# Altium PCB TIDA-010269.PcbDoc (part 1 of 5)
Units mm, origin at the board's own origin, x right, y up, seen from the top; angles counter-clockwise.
Board outline 87.61 x 53.51 mm, 8 copper layers (Top Layer, GND1, Signal 1, Power 1, Power 2, Signal 2, Layer 1, Bottom Layer), stack 1.645 mm thick; 482 components, 227 nets, 1562 pads, 953 vias.
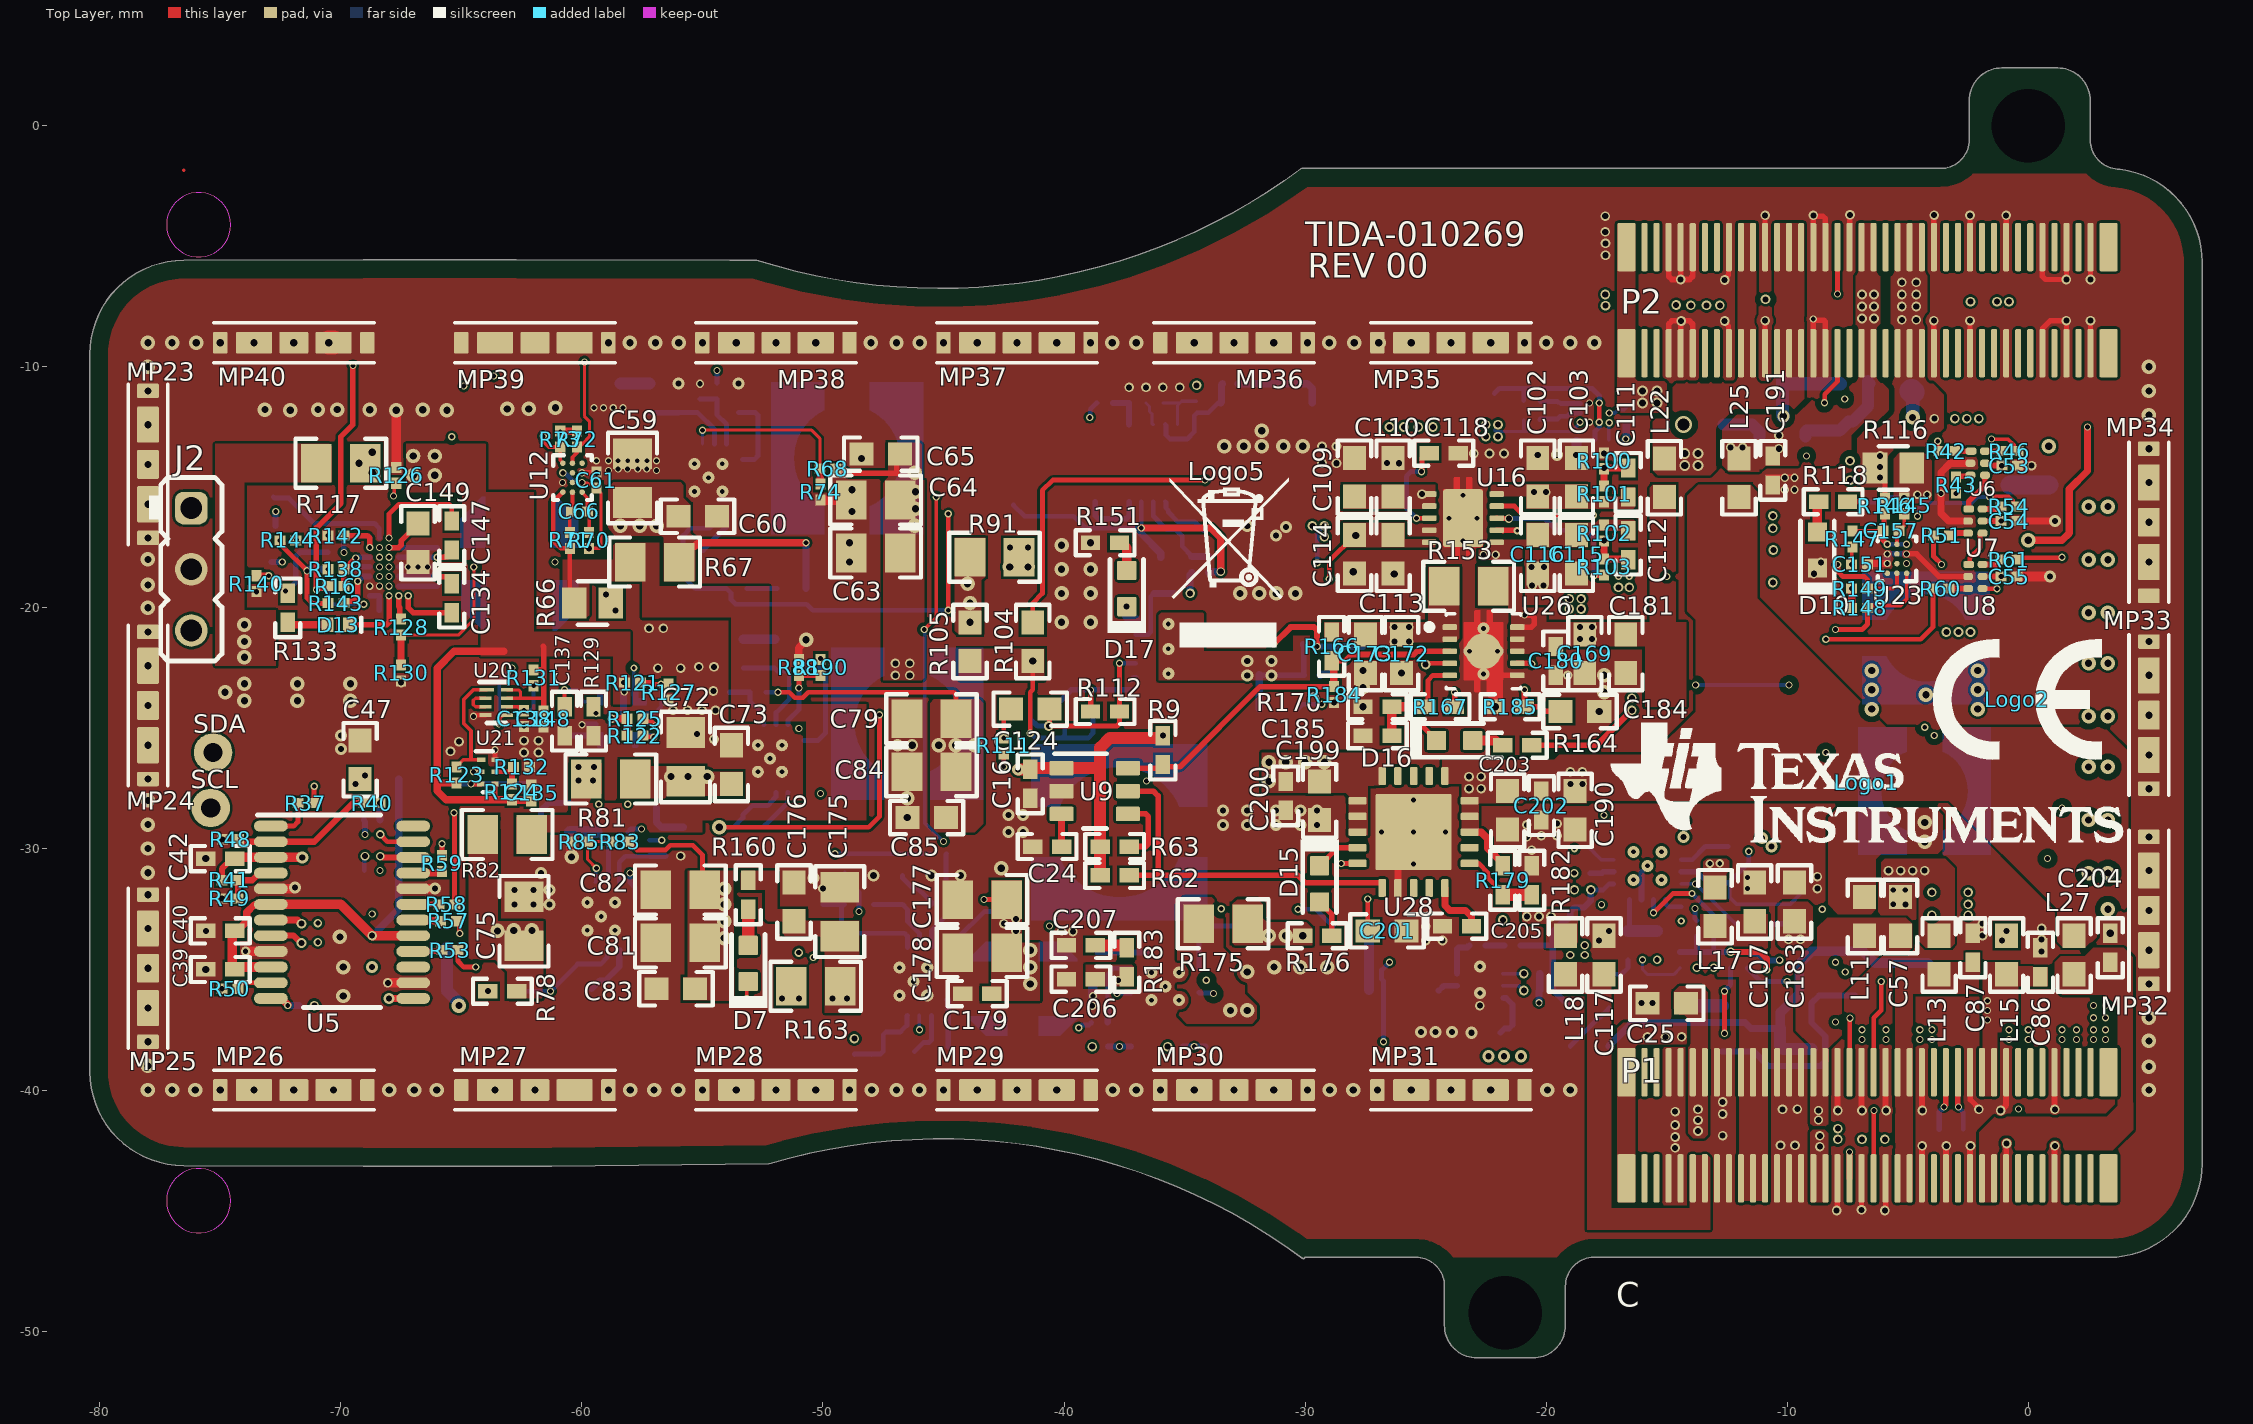
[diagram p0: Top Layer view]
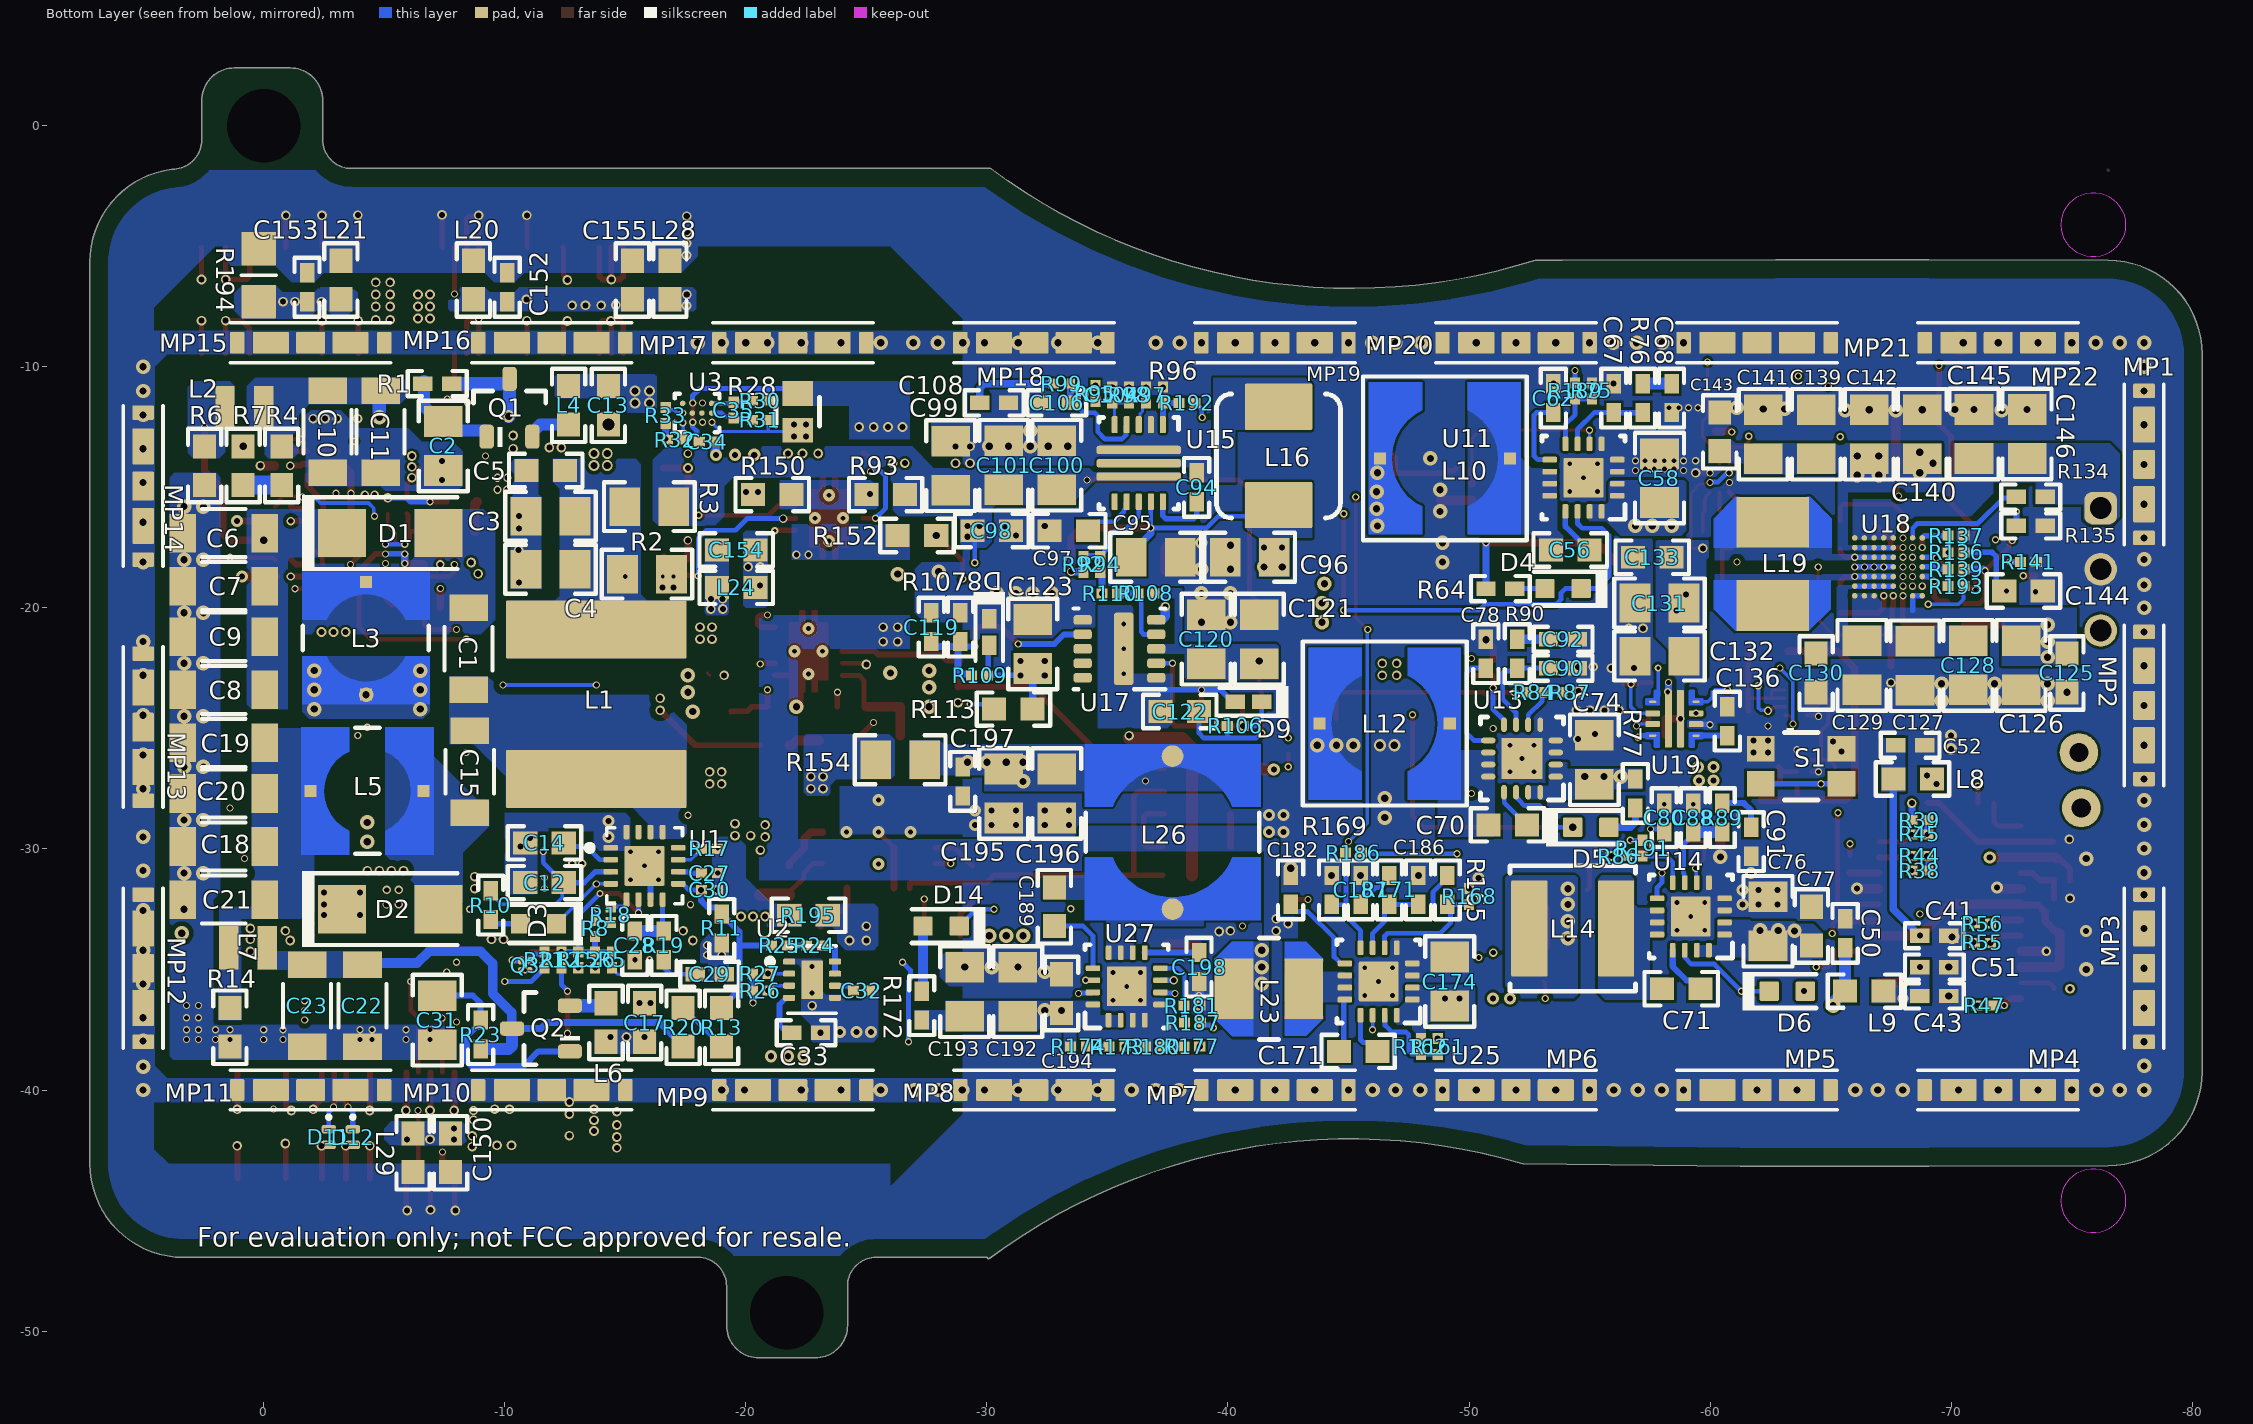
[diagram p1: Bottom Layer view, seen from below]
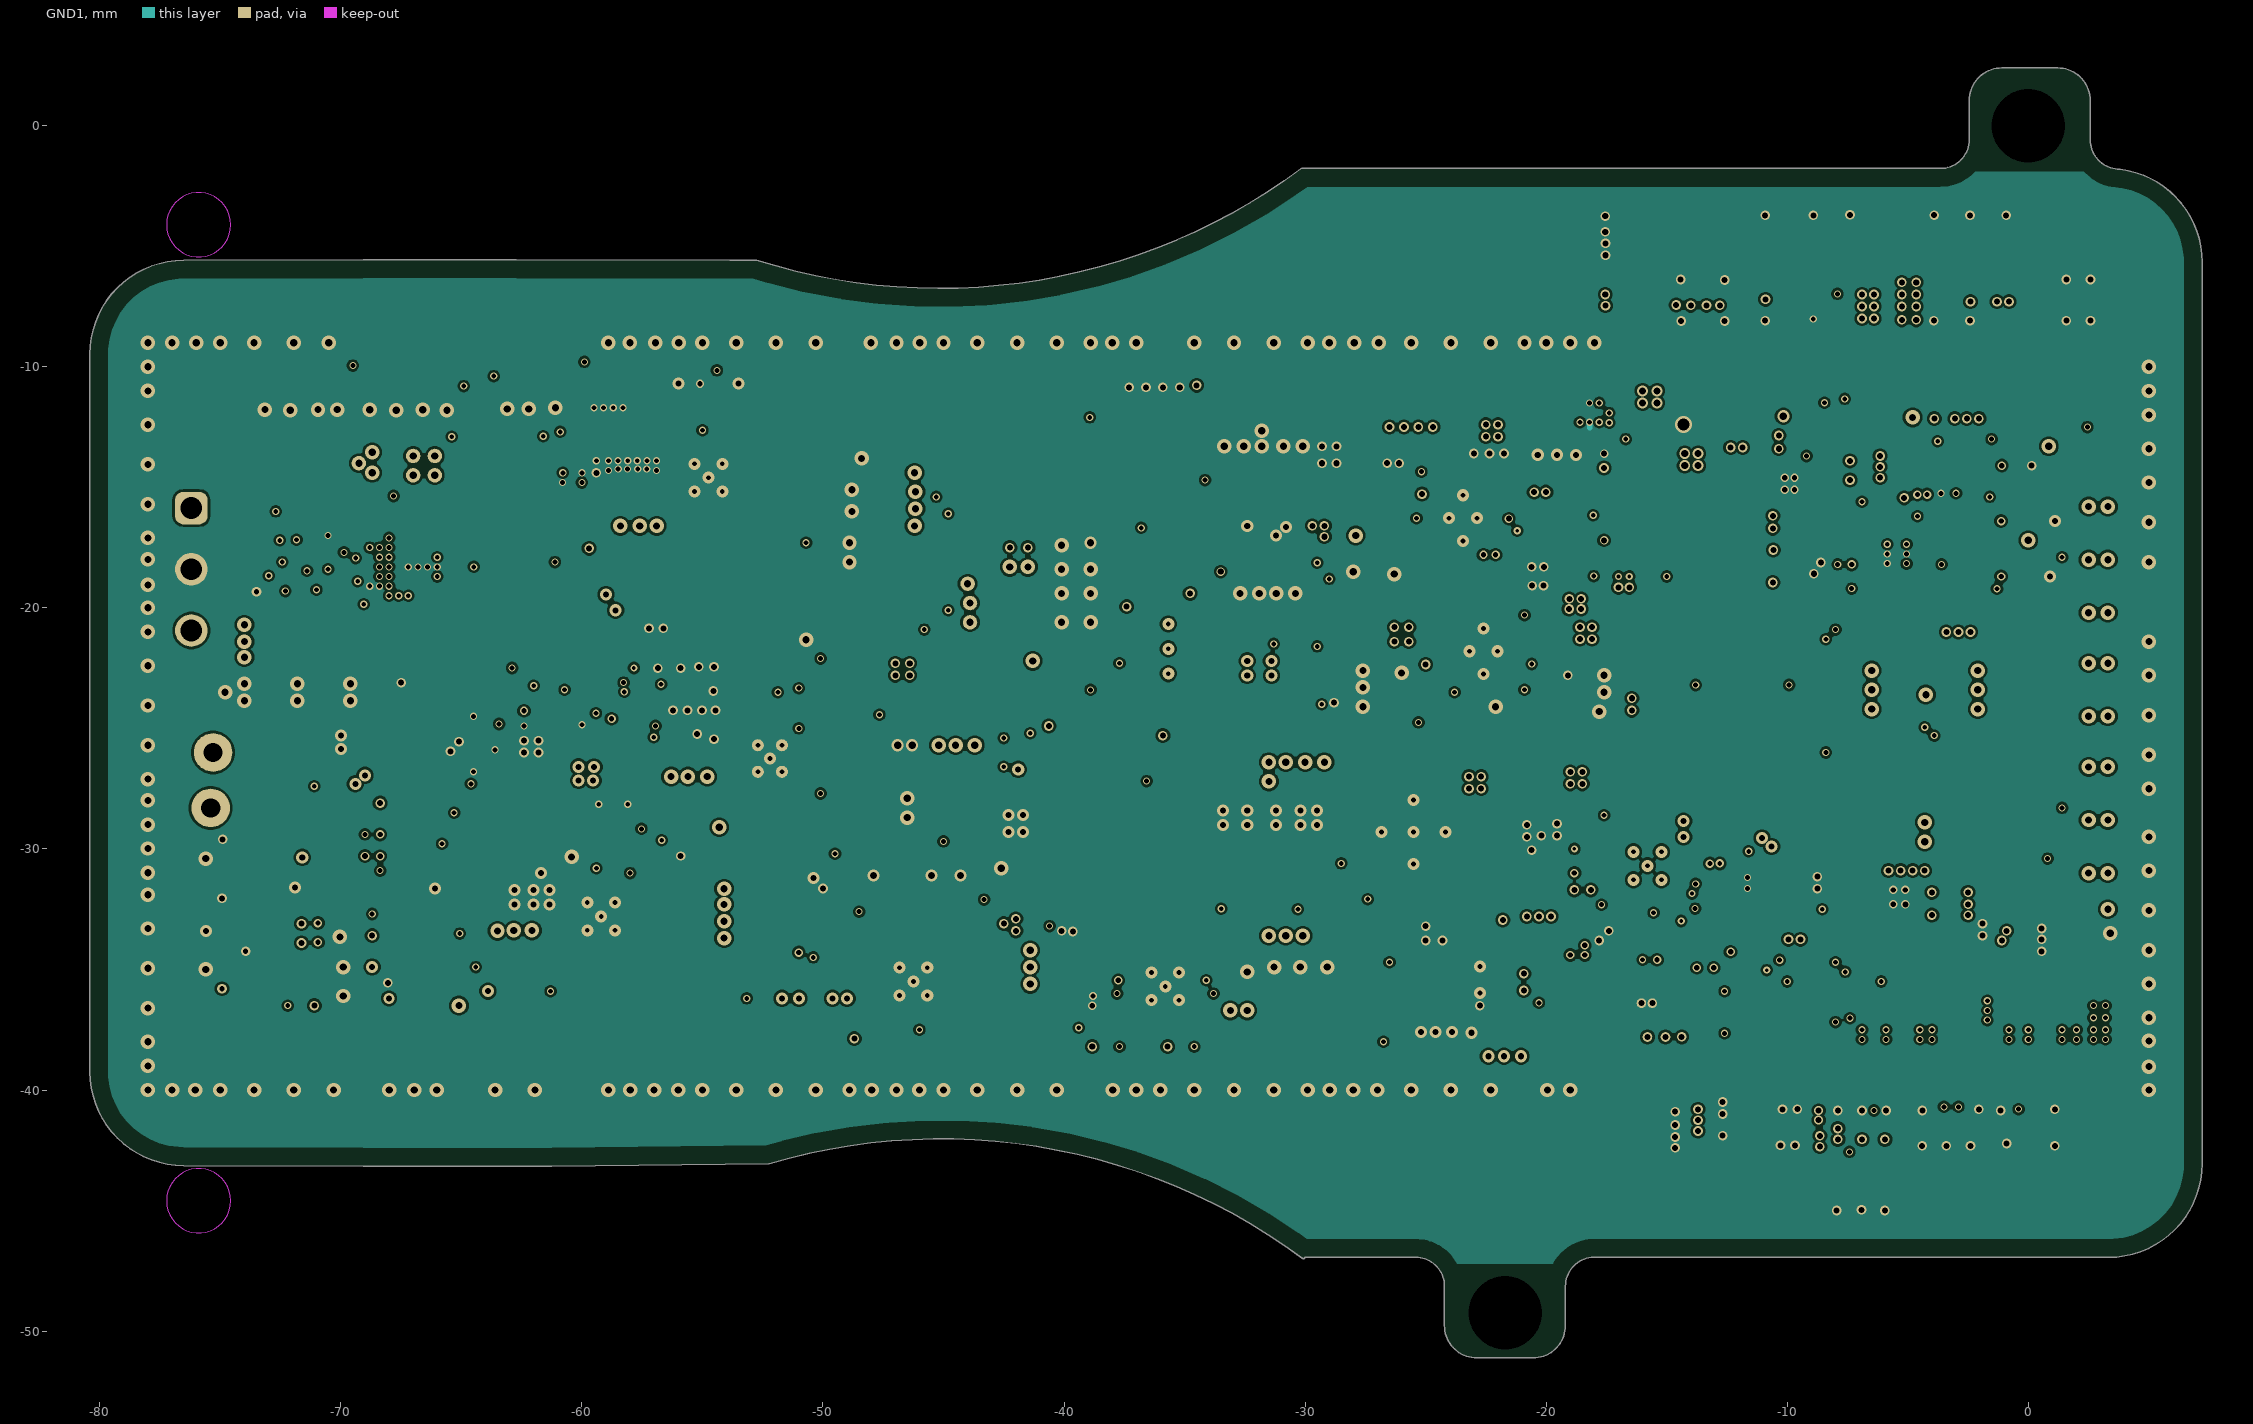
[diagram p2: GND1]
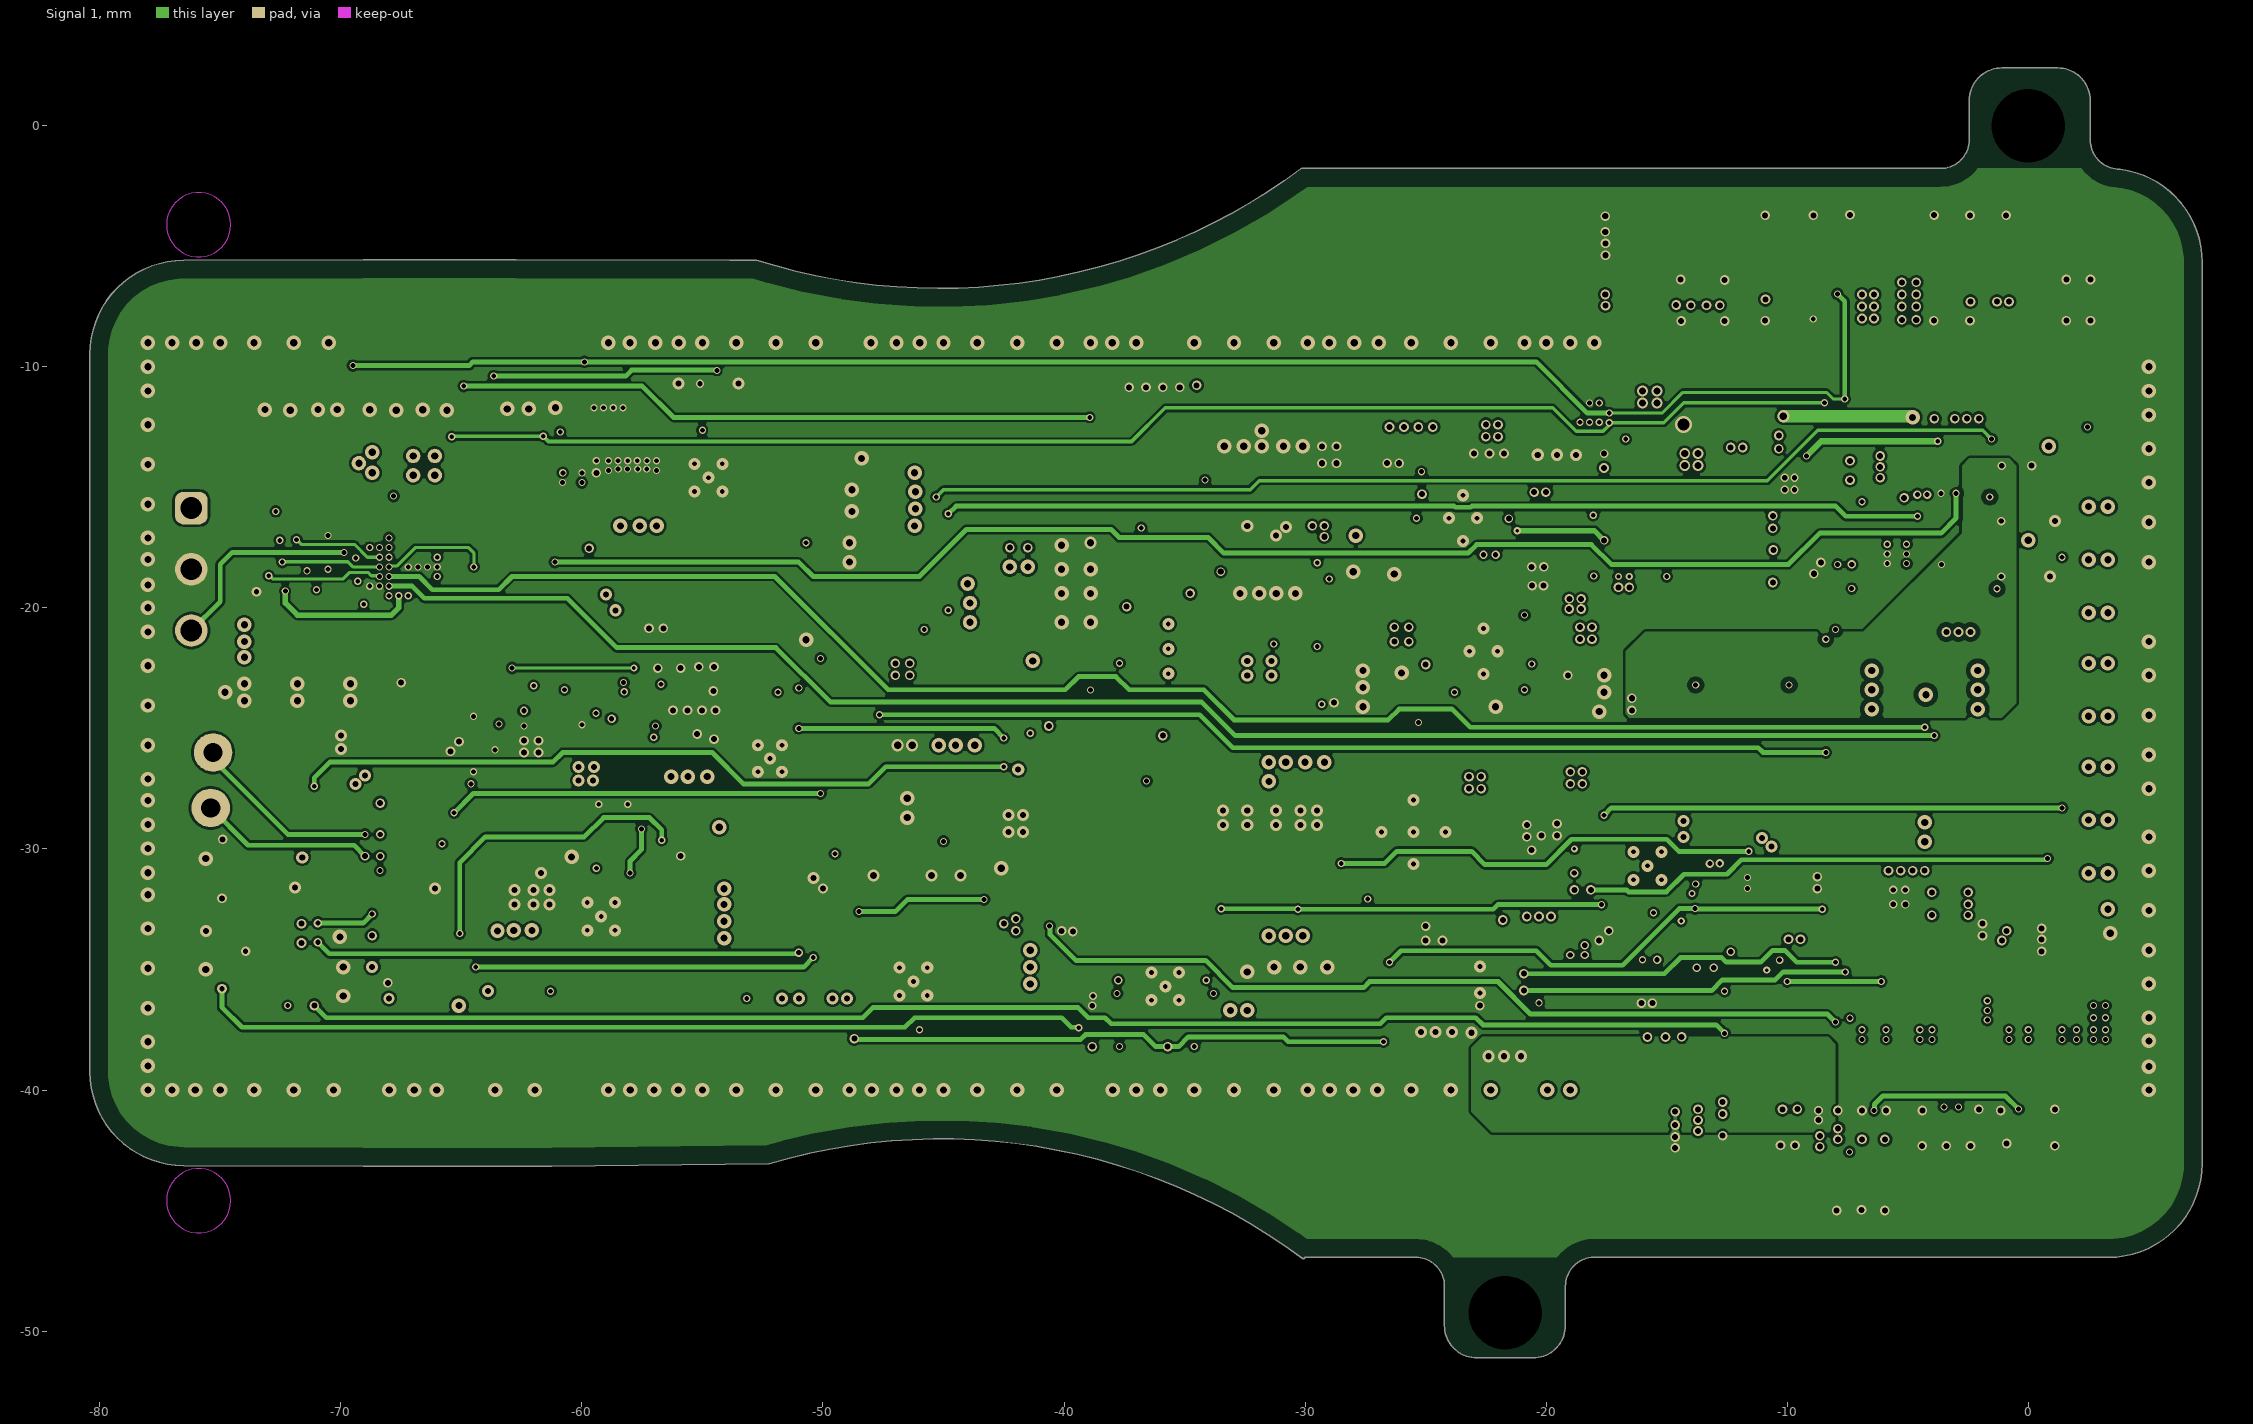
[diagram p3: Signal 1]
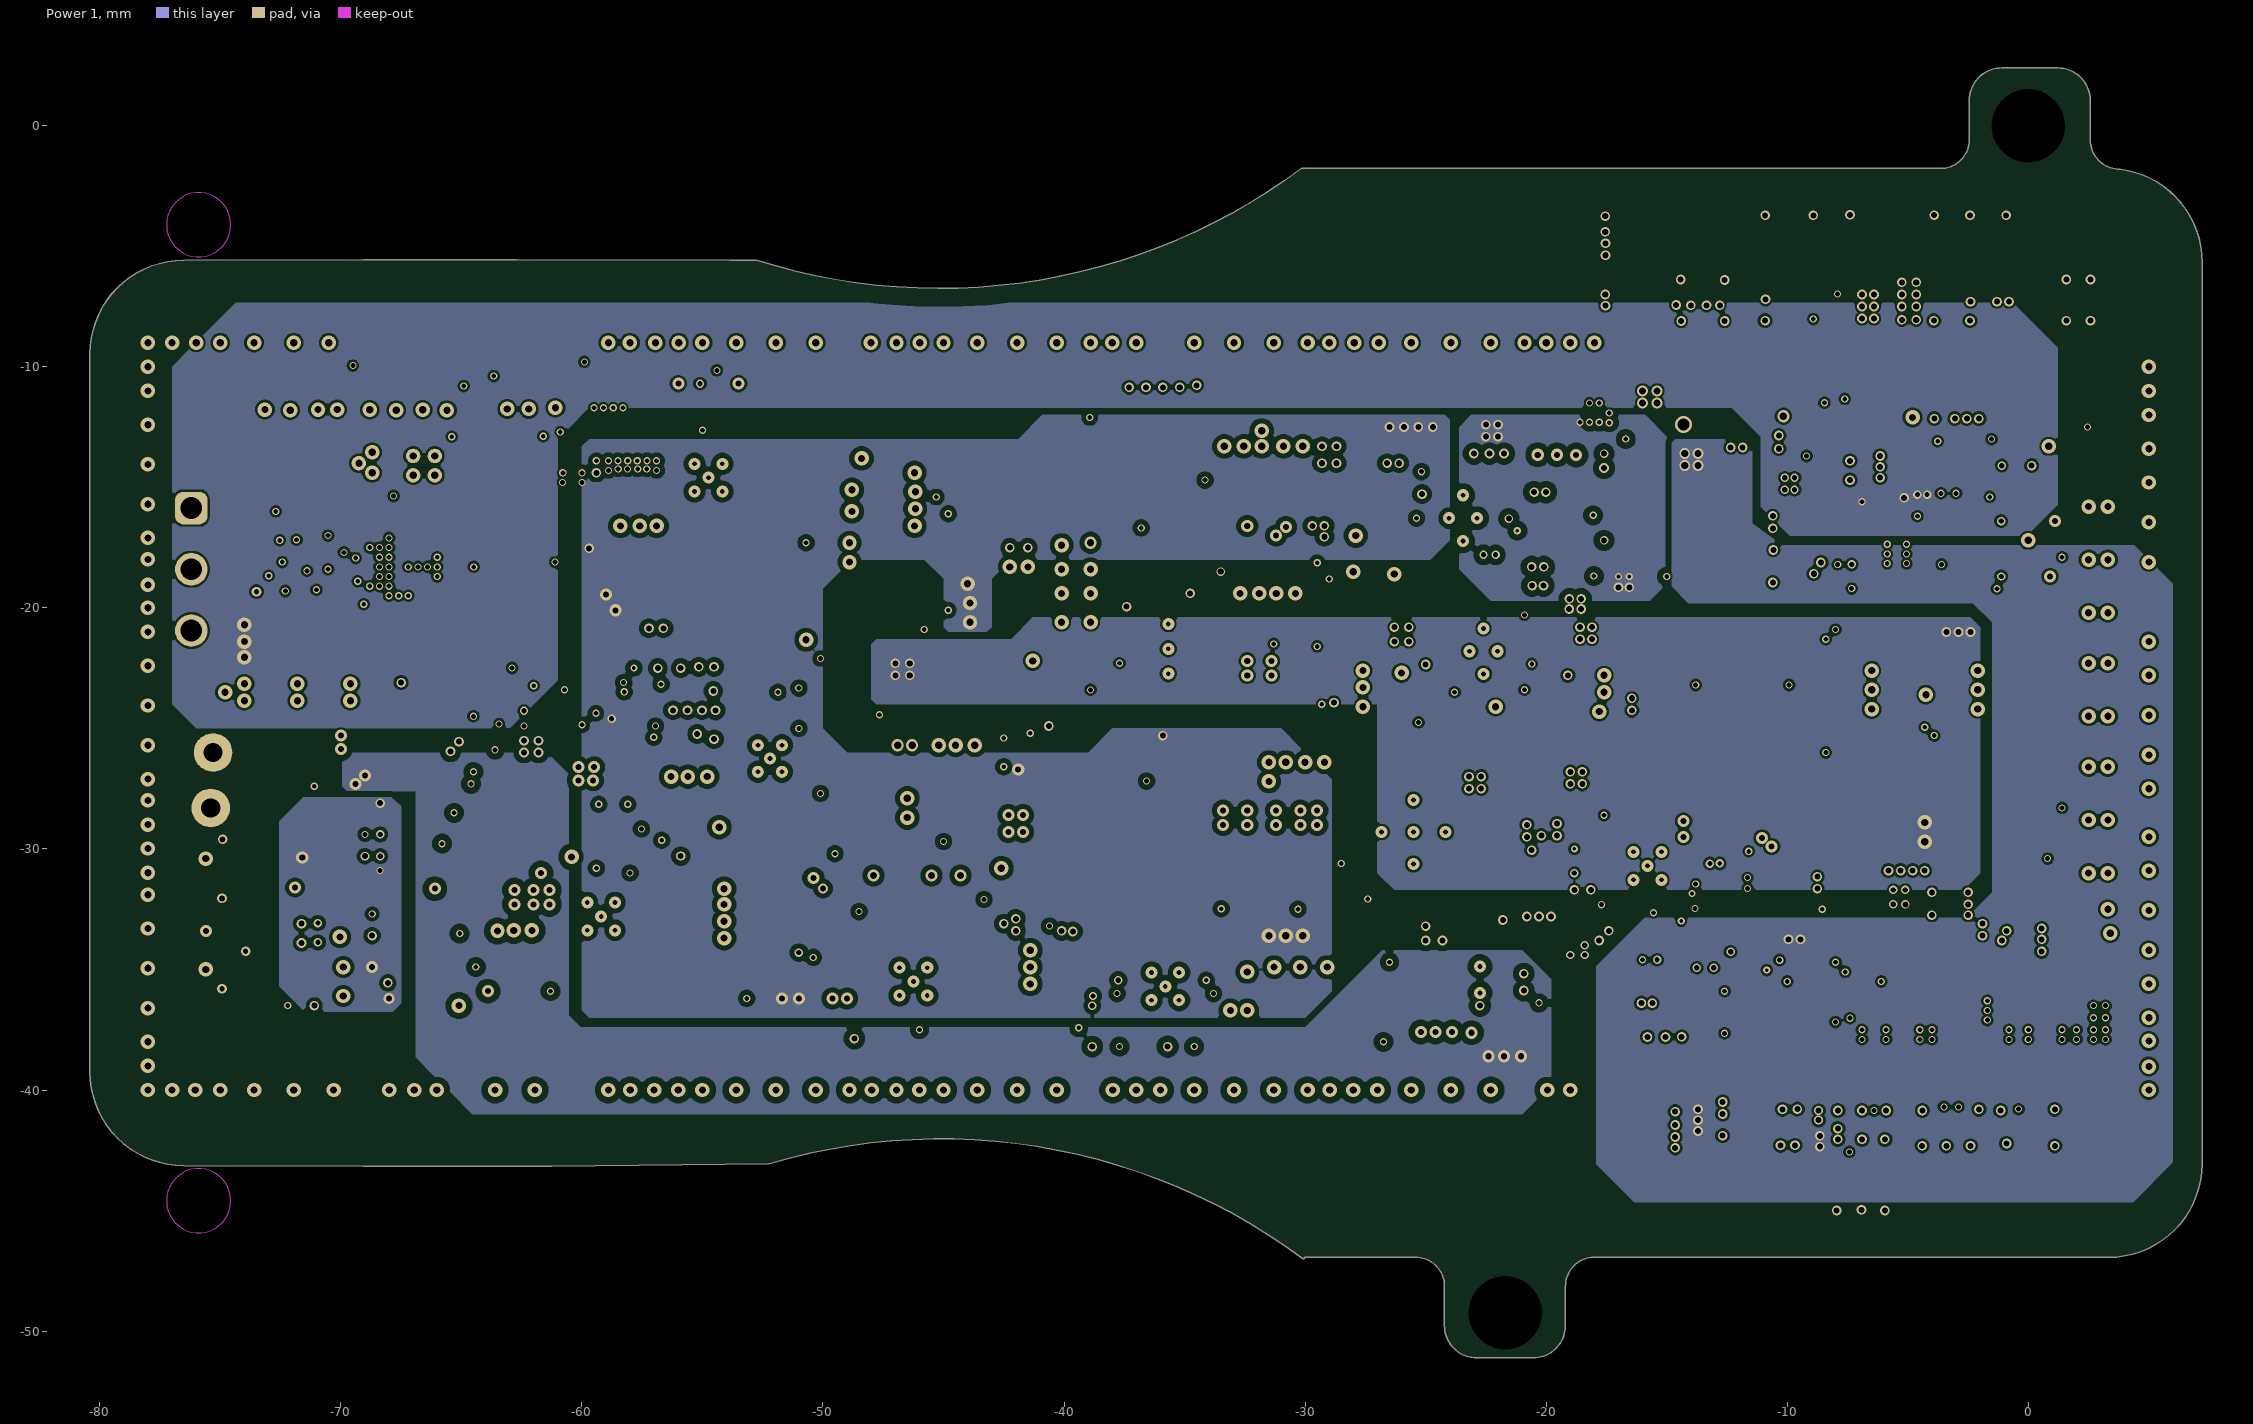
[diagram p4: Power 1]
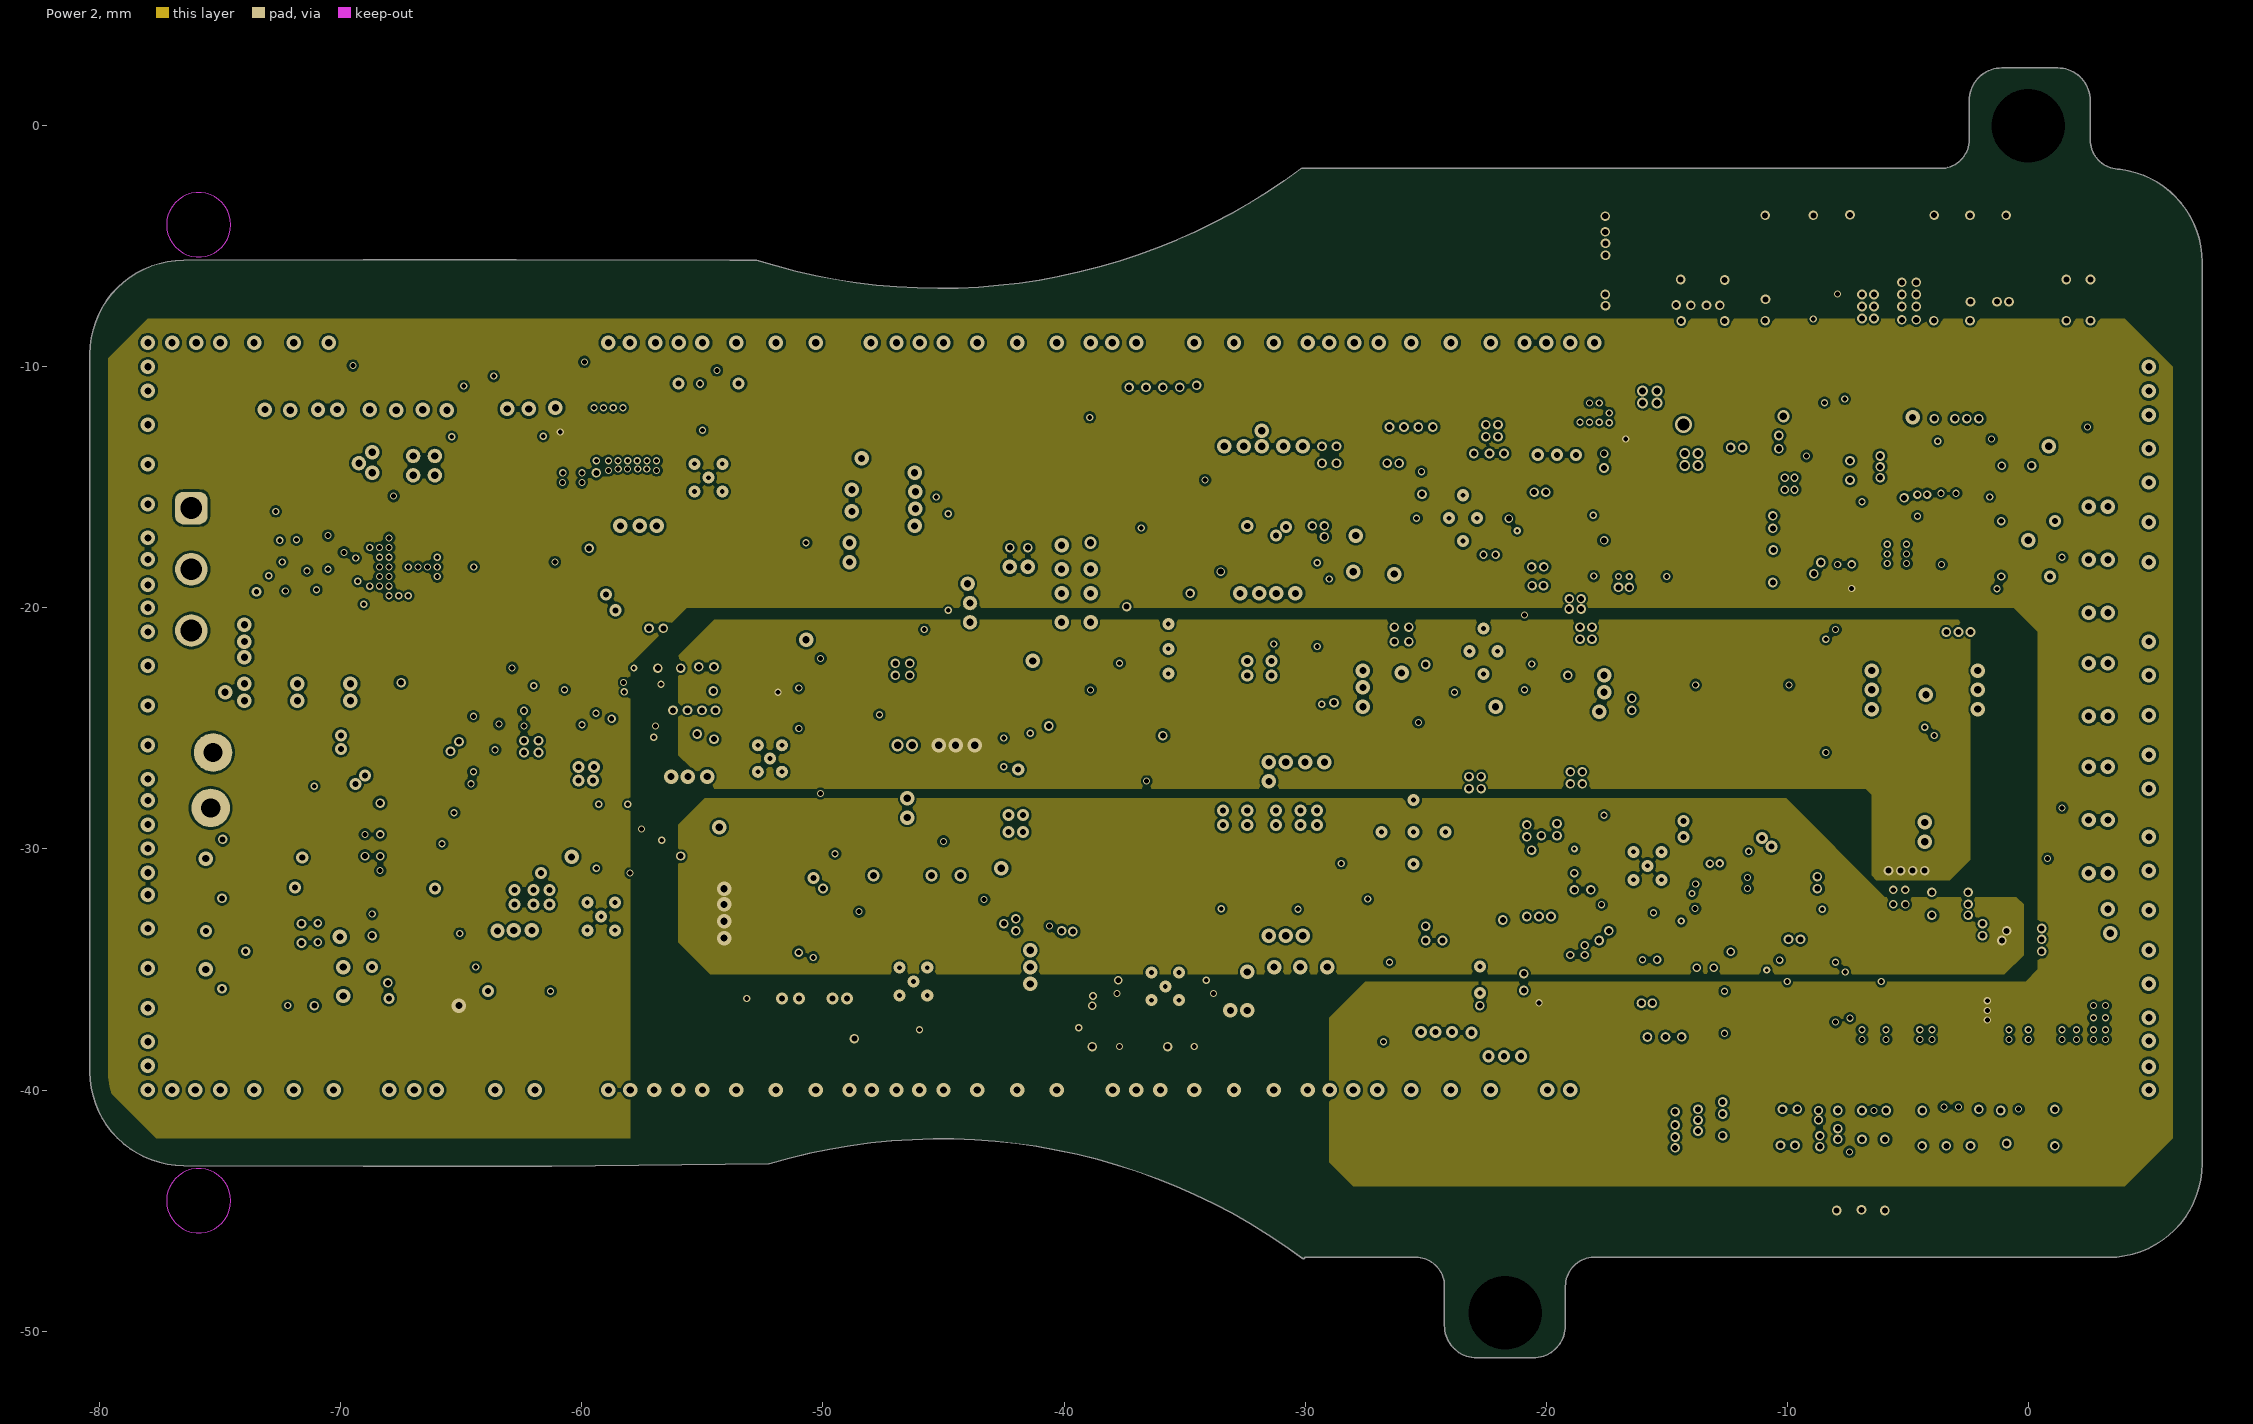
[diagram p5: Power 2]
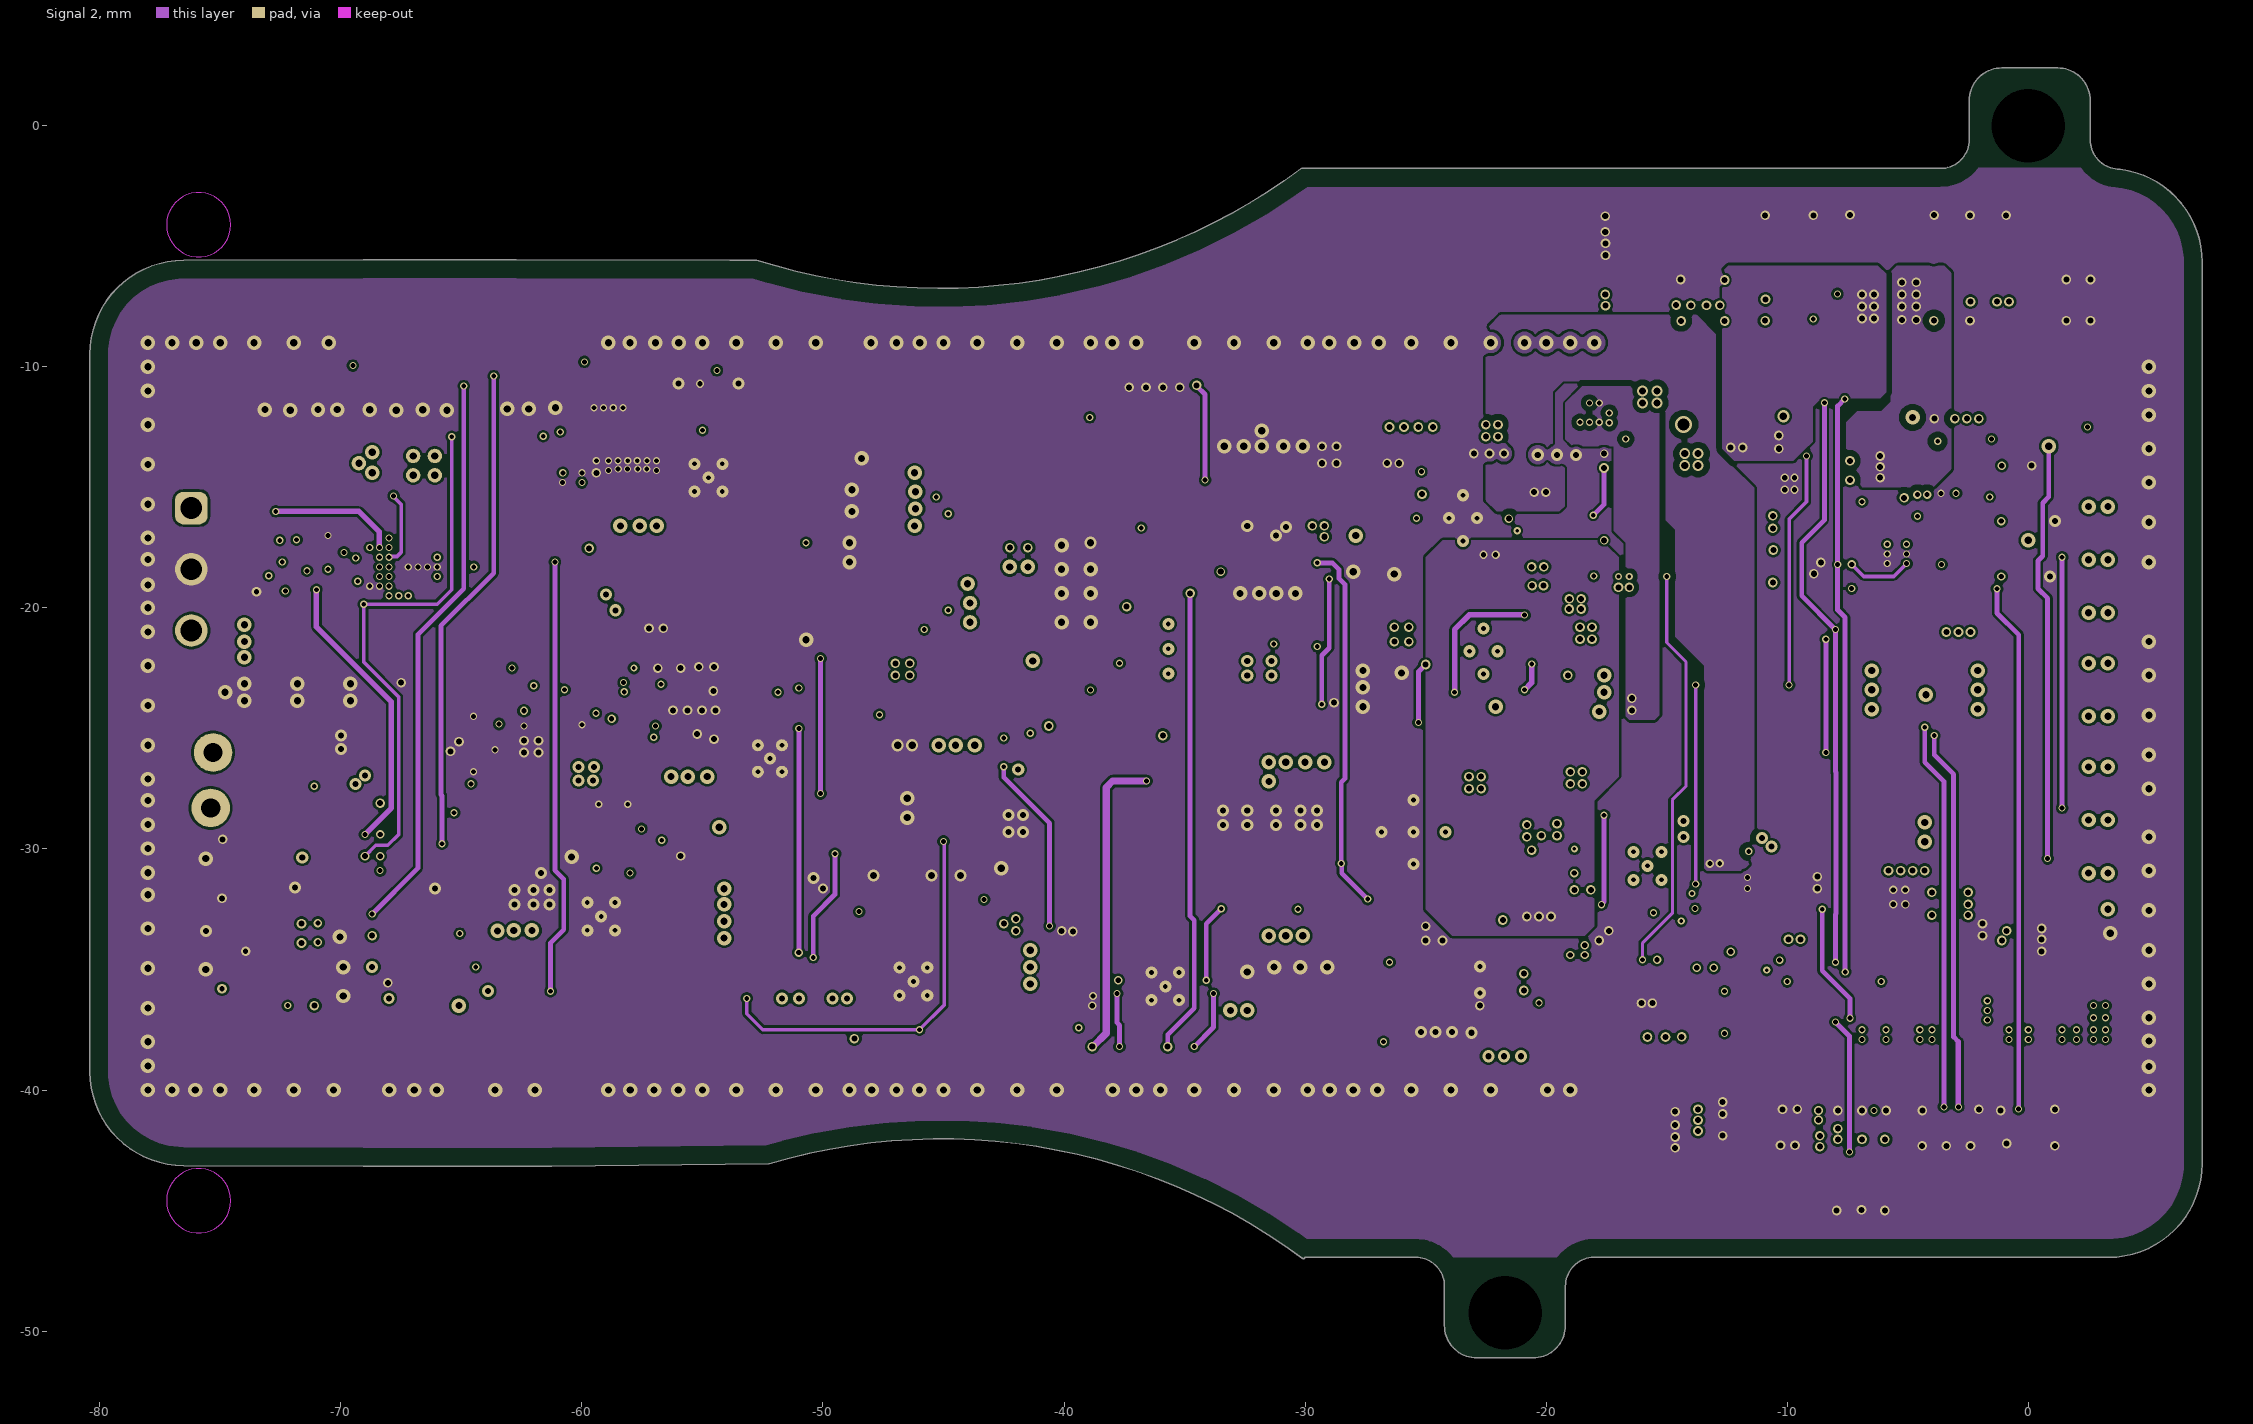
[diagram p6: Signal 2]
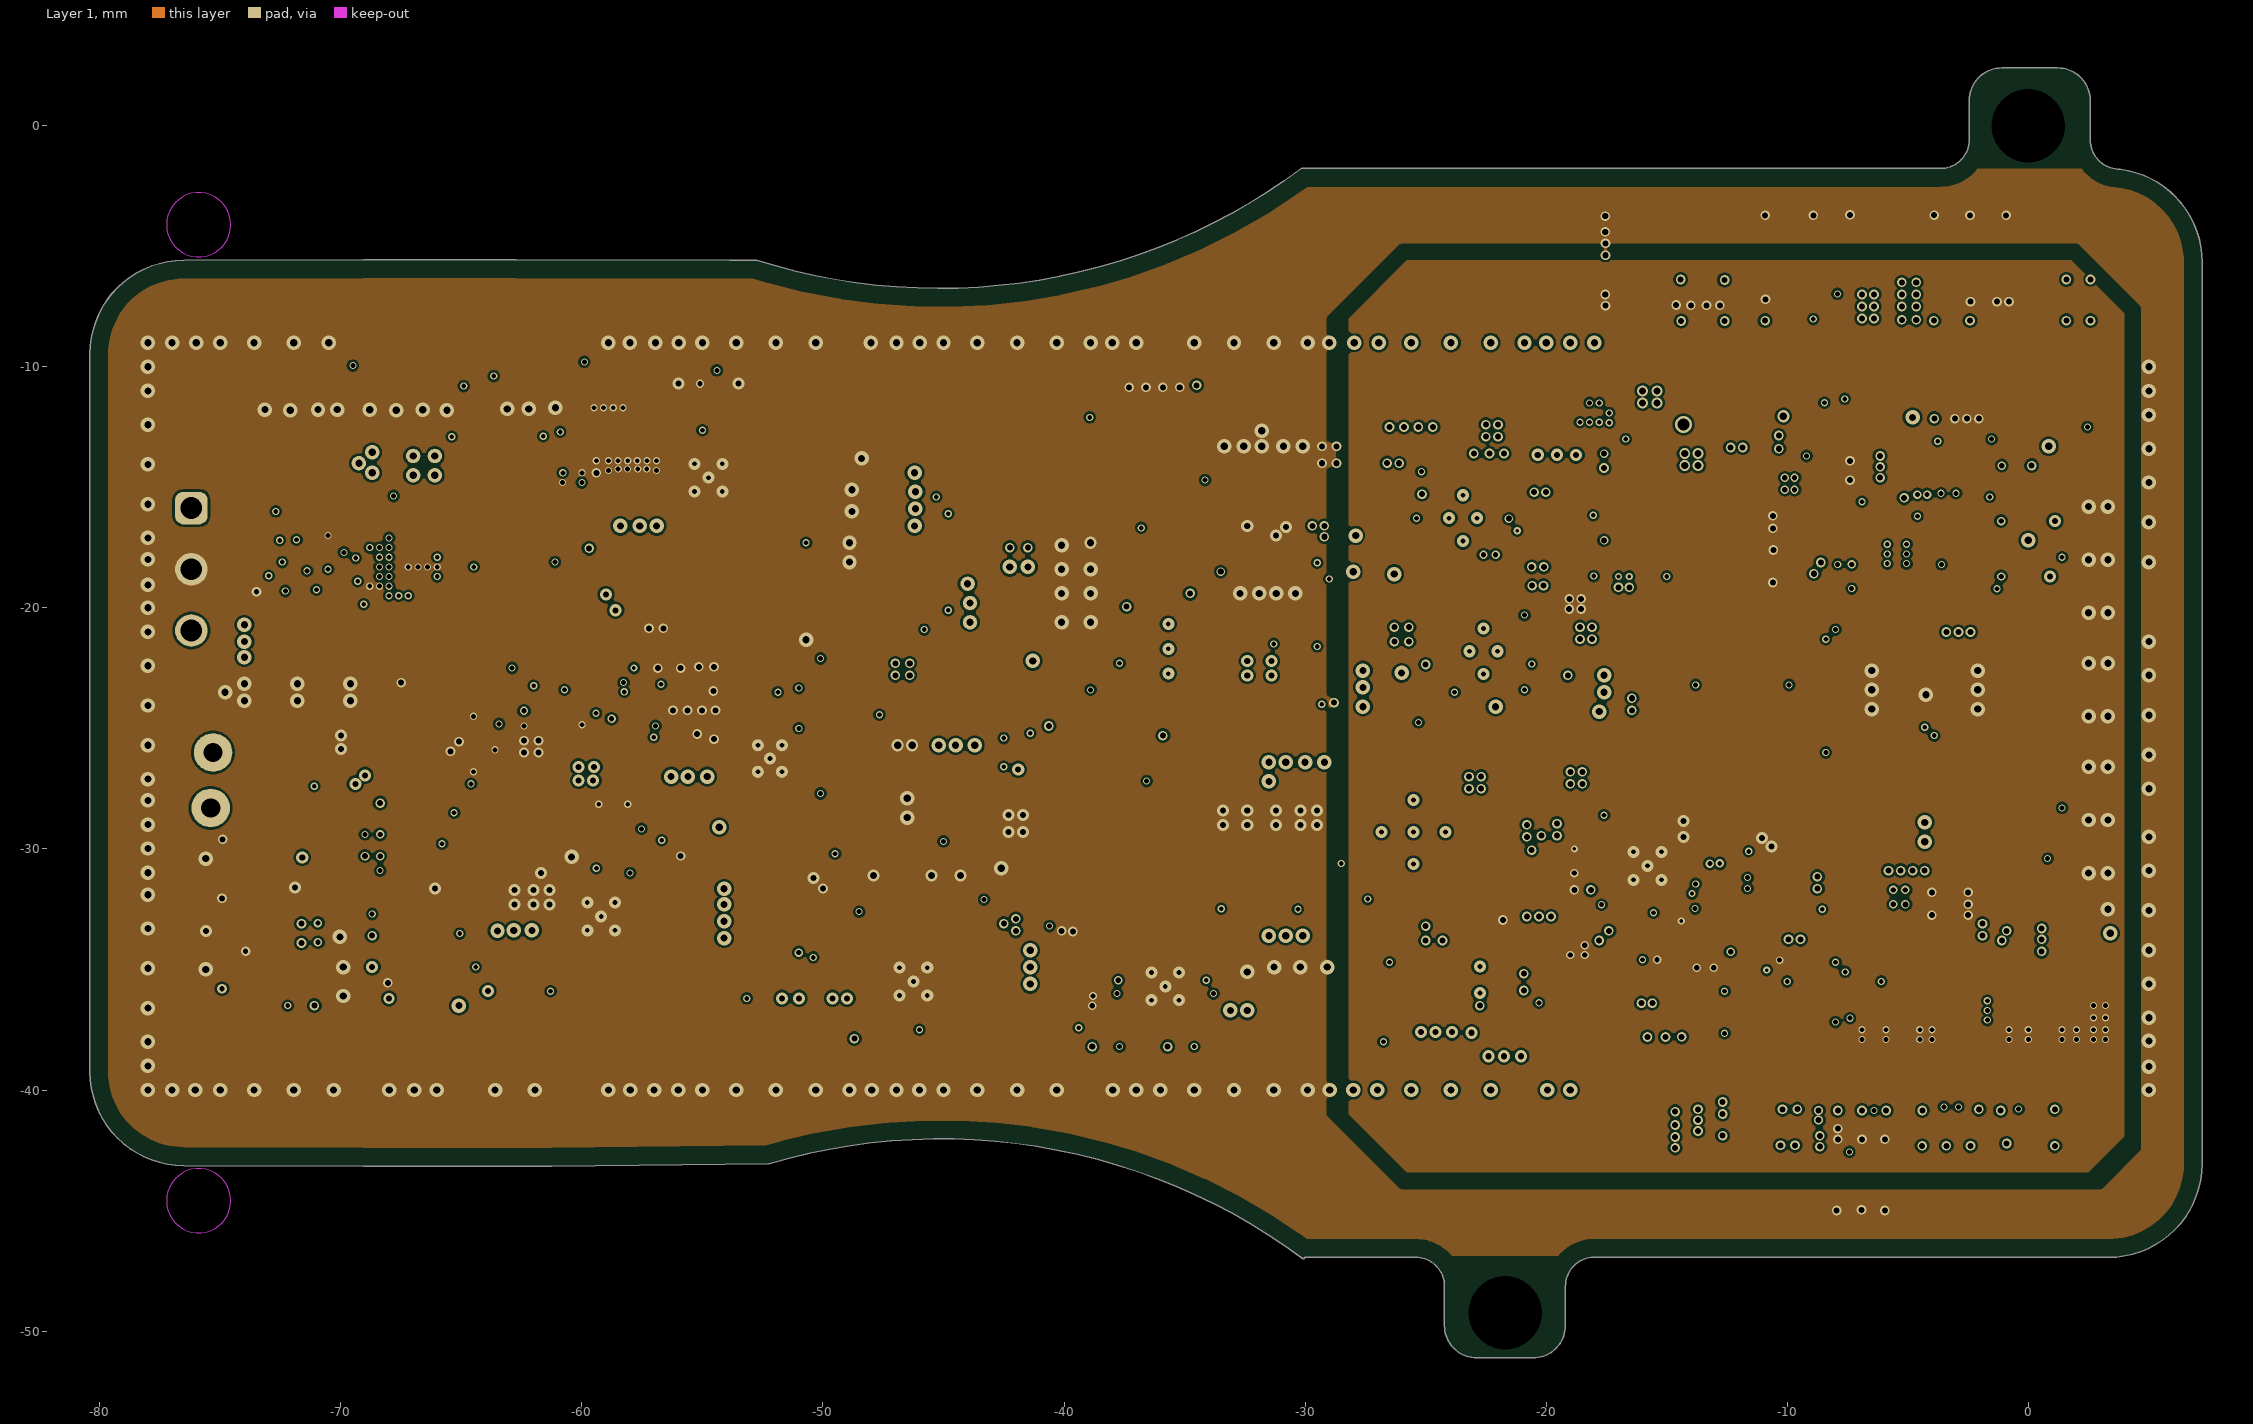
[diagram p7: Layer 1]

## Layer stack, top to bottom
Top Solder: solder mask 0.0254, Solder Resist, Dk 3.5
Top Layer: signal copper 0.07
Dielectric1: core 0.2, FR-4, Dk 4.2
GND1: signal copper 0.0175
Dielectric 2: prepreg 0.2, PP-006, Dk 4.1
Signal 1: signal copper 0.0175
Dielectric 3: prepreg 0.2, PP-006, Dk 4.1
Power 1: signal copper 0.0175
Dielectric 4: prepreg 0.2, PP-006, Dk 4.1
Power 2: signal copper 0.0175
Dielectric 5: prepreg 0.2, PP-006, Dk 4.1
Signal 2: signal copper 0.0175
Dielectric 6: prepreg 0.2, PP-006, Dk 4.1
Layer 1: signal copper 0.0175
Dielectric 1: prepreg 0.2, FR-4, Dk 4.1
Bottom Layer: signal copper 0.07
Bottom Solder: solder mask 0.0254, Solder Resist, Dk 3.5

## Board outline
-76.521,-43.133 -69.071,-43.162 -61.266,-43.162 -61.248,-43.159 -52.255,-43.062 -52.232,-43.058 cw(c-45.102,-67.162) -30.12,-46.979 ccw(c-30.074,-46.917) -30.002,-46.943 -25.412,-46.943 cw(c-25.412,-48.136) -24.219,-48.136 -24.219,-49.767 ccw(c-22.872,-49.767) -22.872,-51.114 -20.549,-51.114 ccw(c-20.549,-49.767) -19.202,-49.767 -19.202,-48.136 cw(c-18.006,-48.136) -17.927,-46.943 -17.922,-46.943 3.32,-46.943 ccw(c3.32,-43.056) 7.206,-43.057 7.206,-43.056 7.206,-5.661 7.206,-5.66 ccw(c3.32,-5.661) 3.814,-1.806 3.802,-1.805 cw(c3.79,-0.581) 2.566,-0.581 2.566,1.05 ccw(c1.219,1.05) 1.219,2.397 -1.104,2.397 ccw(c-1.104,1.05) -2.451,1.05 -2.451,-0.581 cw(c-3.644,-0.581) -3.644,-1.774 -30.134,-1.774 -30.188,-1.796 cw(c-45.171,18.387) -52.76,-5.576 -52.783,-5.572 -53.873,-5.572 -62.72,-5.551 -69.071,-5.551 -76.521,-5.584 ccw(c-76.52,-9.471) -80.407,-9.471 -80.407,-39.246 ccw(c-76.52,-39.246)

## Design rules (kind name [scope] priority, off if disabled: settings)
AcuteAngle [All] p1: minimum=4.50000000000000E+0001 checktracksonly=FALSE
AssemblyTestPointUsage [All] p1: valid=2
BoardOutlineClearance BoardOutlineClearance_MountingHoles [OnCopper and InComponentClass('Mounting Holes')] p1: gap=1.016 ignorepadtopadclearanceinfootprint=FALSE
BoardOutlineClearance BoardOutlineClearance_Poly [OnCopper and IsPoly] p2: gap=0.762 ignorepadtopadclearanceinfootprint=FALSE
BoardOutlineClearance [OnCopper and Not InComponentClass('Logo') and not InComponentClass('FiducialMark') and not InRegion(1000,500,4000,800) and not InPoly] p3: gap=0.508 ignorepadtopadclearanceinfootprint=FALSE
Clearance Clearance_1 [All] p1: gap=0.1 ignorepadtopadclearanceinfootprint=TRUE except(0: Arc-Hole Track-Hole SMDPad-Hole THPad-Hole Via-Hole Fill-Hole Poly-Hole Region-Hole Text-Hole)
ComponentOrientations [All] p1: allowedrotations=1
DiffPairsRouting Diff_100 [InDifferentialPairClass('All Differential Pairs')] p1: maxlimit=0.178 minlimit=0.152 mostfreqgap=0.178 toplayer_maxgap=0.152 toplayer_prefgap=0.152 toplayer_minwidth=0.127 toplayer_maxwidth=0.127 toplayer_prefwidth=0.127 midlayer1_mingap=0.178 midlayer1_minwidth=0.102 midlayer1_maxwidth=0.102 midlayer1_prefwidth=0.102 midlayer2_mingap=0.178 midlayer2_minwidth=0.102 midlayer2_maxwidth=0.102 midlayer2_prefwidth=0.102 midlayer3_mingap=0.178 midlayer3_minwidth=0.102 midlayer3_maxwidth=0.102 midlayer3_prefwidth=0.102 midlayer4_mingap=0.178 midlayer4_minwidth=0.102 midlayer4_maxwidth=0.102 midlayer4_prefwidth=0.102 midlayer5_mingap=0.178 midlayer5_minwidth=0.102 midlayer5_maxwidth=0.102 midlayer5_prefwidth=0.102 midlayer6_mingap=0.178 midlayer6_minwidth=0.102 midlayer6_maxwidth=0.102 midlayer6_prefwidth=0.102 bottomlayer_maxgap=0.152 bottomlayer_prefgap=0.152 bottomlayer_minwidth=0.127 bottomlayer_maxwidth=0.127 bottomlayer_prefwidth=0.127 maxuncoupledlength=25.4
DiffPairsRouting [All] p2 off: maxlimit=0.254 minlimit=0.254 mostfreqgap=0.254 toplayer_minwidth=0.381 toplayer_maxwidth=0.381 toplayer_prefwidth=0.381 midlayer1_minwidth=0.381 midlayer1_maxwidth=0.381 midlayer1_prefwidth=0.381 midlayer2_minwidth=0.381 midlayer2_maxwidth=0.381 midlayer2_prefwidth=0.381 midlayer3_minwidth=0.381 midlayer3_maxwidth=0.381 midlayer3_prefwidth=0.381 midlayer4_minwidth=0.381 midlayer4_maxwidth=0.381 midlayer4_prefwidth=0.381 midlayer5_minwidth=0.381 midlayer5_maxwidth=0.381 midlayer5_prefwidth=0.381 midlayer6_minwidth=0.381 midlayer6_maxwidth=0.381 midlayer6_prefwidth=0.381 bottomlayer_minwidth=0.381 bottomlayer_maxwidth=0.381 bottomlayer_prefwidth=0.381 maxuncoupledlength=12.7
FabricationTestPointUsage TestPointUsage [All] p1: valid=2 allowmultiple=FALSE
FabricationTestpoint Testpoint [All] p1: side=3 testpointundercomponent=TRUE minsize=1.016 maxsize=2.54 preferedsize=1.524 minholesize=0 maxholesize=1.016 preferedholesize=0.813 testpointgrid=0.025 allowsidetop=TRUE allowsidebottom=TRUE usegrid=TRUE gridtolerance=0
FanoutControl Fanout_LCC [IsLCC] p1: bgadir=Out bgaviamode=Centered fanoutstyle=Auto fanoutdirection=Alternating viagrid=0.025 // Fanout_LCC (Default Rule)
FanoutControl Fanout_BGA [HasFootprint('ACP0196A-MFG')] p2: bgadir=In bgaviamode=Centered fanoutstyle=UnderPads fanoutdirection=InOnly viagrid=0.025 // Fanout_BGA (Default Rule)
FanoutControl Fanout_Default [All] p4: bgadir=Out bgaviamode=Closest fanoutstyle=Auto fanoutdirection=Alternating viagrid=0.025 // Fanout_Default (Default Rule)
FanoutControl Fanout_Small [(CompPinCount < 5)] p5: bgadir=Out bgaviamode=Centered fanoutstyle=Auto fanoutdirection=OutThenIn viagrid=0.025 // Fanout_Small (Default Rule)
HoleSize [IsPad] p1: absolutevalues=TRUE maxlimit=4.064 minlimit=0.2 maxpercent=80.000 minpercent=20.000
Length Length_TX_SEN_SCLK [InNetClass('TX_SEN_SCLK')] p1: maxlimit=64.084 minlimit=64.059
Length Length_RX_SYNC_CLK [InNetClass('RX_SYNC_CLK')] p2: maxlimit=66.573 minlimit=66.599
Length Length_TX_SYNC_CLK [InNetClass('TX_SYNC_CLK')] p3: maxlimit=76.937 minlimit=76.962
Length Length_TX_SDIN1 [InNetClass('TX_SDIN1')] p4: maxlimit=64.084 minlimit=64.059
Length Length_TX_SDIN2 [InNetClass('TX_SDIN2')] p5: maxlimit=83.058 minlimit=83.083
Length Length_DOUT1PM [InNetClass('DOUT1_PM')] p6: maxlimit=23.622 minlimit=23.597
Length Length_DOUT2PM [InNetClass('DOUT2_PM')] p7: maxlimit=23.876 minlimit=23.851
MatchedLengths "across the pair" [All] p1: tolerance=0.025 checknetsindiffpair=FALSE checkdiffpairvsdiffpair=TRUE checkxsignals=TRUE checkothers=TRUE
MatchedLengths "With in pair" [All] p2: tolerance=0.025 checknetsindiffpair=TRUE checkdiffpairvsdiffpair=FALSE checkxsignals=FALSE checkothers=FALSE
MinimumAnnularRing MinimumAnnularRing_ThermalPadVias [IsVia and InAnyComponent] p1: minimumring=0.05
MinimumAnnularRing [All] p2: minimumring=0.05
MinimumSolderMaskSliver MinimumSolderMaskSliver_Logo [InComponentClass('Logo') vs InComponentClass('Logo')] p1: minsoldermaskwidth=0.018
MinimumSolderMaskSliver [All] p2: minsoldermaskwidth=0.1
NetsToIgnore [All] p1:
PermittedLayers [All] p1: toplayerpermitted=TRUE bottomlayerpermitted=TRUE
PlaneClearance [All] p1: clearance=0.25
PlaneConnect [All] p1: planeconnectstyle=Direct reliefexpansion=0.254 reliefentries=4 reliefconductorwidth=0.254 reliefairgap=0.254
PolygonConnect [All] p1: connectstyle=Direct reliefconductorwidth=0.508 reliefentries=4 polygonreliefangle="90 Angle" airgapwidth=0.254
RoomDefinition "Sht05--TX-RX Supply 1.8V and 1.15V" [InComponentClass('Sht05--TX-RX Supply 1.8V and 1.15V')] p1: confinementstyle=ConfineIn formatcopy=TRUE lockcomponents=FALSE outline -87.544,-89.968 39.456,-89.968 39.456,37.032 -87.544,37.032
RoutingCorners [All] p1: cornerstyle=45-Degree minsetback=0.1 maxsetback=0.2
RoutingVias RoutingVias_1 [All] p1: holewidth=0.2 width=0.3 viastyle="Through Hole" minholewidth=0.2 minwidth=0.3 maxholewidth=0.2 maxwidth=0.3
SilkToBoardRegionClearance [Not ((IsComment or IsDesignator) And (Hide <> 'False')) and not InRegion(1000,500,4000,800)] p1:
SilkToSilkClearance SilkToSilkClearance_Pb-FreeLogo [(HasFootprint('Pb-Free_Overlay_Medium') OR HasFootprint('Pb-Free_Overlay_Small')) vs (HasFootprint('Pb-Free_Overlay_Medium') OR HasFootprint('Pb-Free_Overlay_Small'))] p1: silktosilkclearance=0
SilkToSilkClearance [All] p2: silktosilkclearance=0.102
SilkToSolderMaskClearance SilkToComponentPadClearance [(IsPad or IsFill or IsRegion) and InAnycomponent] p1: minsilkscreentomaskgap=0.127 clearancetoexposedcopper=TRUE
SilkToSolderMaskClearance "Silk to Solder Mask Opening" [All] p2: minsilkscreentomaskgap=0.102 clearancetoexposedcopper=FALSE
SolderMaskExpansion [All] p1: expansion=0.05 istentingtop=FALSE
Width Width_1 [All] p1: maxlimit=1 minlimit=0.13 preferedwidth=0.2
14 further rules are at their usual default settings.

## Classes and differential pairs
component class "Sht05--TX-RX Supply 1.8V and 1.15V": C16 C24 C25 C169 C171 C172 C173 C174 C175 C176 C177 C178 C179 C180 C181 C182 C183 C184 C185 C186 C187 C189 C190 C191 C192 C193 C194 C195 C196 C197 C198 C199 C200 C201 C202 C203 C204 C205 C206 C207 D7 D14 D15 D16 L22 L23 L25 L26 L27 R9 R62 R63 R153 R154 R160 R161 R162 R163 R164 R165 R166 R167 R168 R169 R170 R171 R172 R173 R174 R175 R176 R177 R179 R180 R181 R182 R183 R184 R185 R186 R187 U9 U25 U26 U27 U28
component class Sht01--EVM_Hardware: !PCB Logo1 Logo2 Logo3 Logo5 MP1 MP2 MP3 MP4 MP5 MP6 MP7 MP8 MP9 MP10 MP11 MP12 MP13 MP14 MP15 MP16 MP17 MP18 MP19 MP20 MP21 MP22 MP23 MP24 MP25 MP26 MP27 MP28 MP29 MP30 MP31 MP32 MP33 MP34 MP35 MP36 MP37 MP38 MP39 MP40 ZZ1 ZZ2 ZZ3 ZZ4
component class AssemblyNote: ZZ1 ZZ2 ZZ3 ZZ4
component class "Sht04--FPGA Power Supply": C56 C57 C58 C59 C60 C61 C62 C63 C64 C65 C66 C67 C68 C70 C71 C72 C73 C74 C75 C76 C77 C78 C79 C80 C81 C82 C83 C84 C85 C86 C87 C88 C90 C91 C92 D4 D5 D6 L10 L11 L12 L13 L14 L15 R64 R66 R67 R68 R70 R71 R72 R73 R74 R75 R76 R77 R78 R81 R82 R83 R84 R85 R86 R87 R88 R89 R90 R189 R190 R191 U11 U12 U13 U14
component class "Sht06--TX Supply +5V and -5V": C94 C95 C96 C97 C98 C99 C100 C101 C102 C103 C104 C106 C107 C108 C109 C110 C111 C112 C113 C114 C115 C116 C117 C118 C119 C120 C121 C122 C123 C124 D8 D9 D17 L16 L17 L18 R91 R92 R93 R94 R95 R96 R97 R98 R99 R100 R101 R102 R103 R104 R105 R106 R107 R108 R109 R110 R111 R112 R113 R150 R151 R152 R192 U15 U16 U17
component class "Sht07--High Voltage Power Supply": C1 C2 C3 C4 C5 C6 C7 C8 C9 C10 C11 C12 C13 C14 C15 C17 C18 C19 C20 C21 C22 C23 C26 C27 C28 C29 C30 C31 C32 C33 C34 C35 C150 C152 C153 C154 C155 D1 D2 D3 L1 L2 L3 L4 L5 L6 L7 L20 L21 L24 L28 L29 Q1 Q2 Q3 R1 R2 R3 R4 R5 R6 R7 R8 R10 R11 R12 R13 R14 R15 R17 R18 R19 R20 R21 R23 R24 R25 R26 R27 R28 R30 R31 R32 R33 R194 R195 U1 U2 U3
component class "Sht02--Input Output Connector": C39 C40 C41 C42 C43 C47 C50 C51 C52 C53 C54 C55 L8 L9 P1 P2 R37 R38 R39 R40 R41 R42 R43 R44 R45 R46 R47 R48 R49 R50 R51 R53 R54 R55 R56 R57 R58 R59 R60 R61 SCL SDA U5 U6 U7 U8
component class "Sht03--Efuse_Power on-Off Controller": C125 C126 C127 C128 C129 C130 C131 C132 C133 C134 C135 C136 C137 C138 C139 C140 C141 C142 C143 C144 C145 C146 C147 C148 C149 C151 C157 D10 D11 D12 D13 J2 L19 R16 R116 R117 R118 R121 R122 R123 R124 R125 R126 R127 R128 R129 R130 R131 R132 R133 R134 R135 R136 R137 R138 R139 R140 R141 R142 R143 R144 R145 R146 R147 R148 R149 R193 S1 U18 U19 U20 U21 U23

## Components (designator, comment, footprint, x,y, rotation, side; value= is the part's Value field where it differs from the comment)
C1 "C3216X7S2A225K160AB" 1206_180 -8.5,-21.7 r90 bottom locked value=2.2uF
C2 "C2012X7S2A105K125AB" 0805_HV -7.45,-13.284 r270 bottom locked value=1uF
C3 "GRM21BR61A476ME15L" 0805_HV -11.9,-16.2 r0 bottom locked value=47uF
C4 "GRM21BR61A476ME15L" 0805_HV -11.9,-18.4 r0 bottom locked value=47uF
C5 "885012206095" 0603 -11.7,-14.3 r0 bottom locked value=0.1uF
C6 "C3216X7S2A225K160AB" 1206_180 1.65,-16.9 r0 bottom locked value=2.2uF
C7 "C3216X7S2A225K160AB" 1206_180 1.65,-19.1 r0 bottom locked value=2.2uF
C8 "C3216X7S2A225K160AB" 1206_180 1.65,-23.4 r0 bottom value=2.2uF
C9 "C3216X7S2A225K160AB" 1206_180 1.65,-21.2 r0 bottom value=2.2uF
C10 "C3216X7S2A225K160AB" 1206_180 -2.65,-12.7 r270 bottom value=2.2uF
C11 "C3216X7S2A225K160AB" 1206_180 -4.85,-12.7 r270 bottom locked value=2.2uF
C12 "GRM188C81E475KE11D" 0603 -11.65,-31.4 r0 bottom value=4.7uF
C13 "GRM188R72A104KA35J" 0603 -14.3,-11.6 r270 bottom value=0.1uF
C14 "GCM188R71C105KA64J" 0603 -11.65,-29.75 r0 bottom locked value=1uF
C15 "C3216X7S2A225K160AB" 1206_180 -8.55,-26.8 r270 bottom value=2.2uF
C16 "GRM155R61E104KA87D" 0402 -41.4,-27.3 r270 top locked value=0.1uF
C17 "GRM188R72A104KA35J" 0603 -15.8,-37.2 r270 bottom value=0.1uF
C18 "C3216X7S2A225K160AB" 1206_180 1.65,-29.9 r180 bottom value=2.2uF
C19 "C3216X7S2A225K160AB" 1206_180 1.65,-25.6 r180 bottom value=2.2uF
C20 "C3216X7S2A225K160AB" 1206_180 1.65,-27.7 r180 bottom value=2.2uF
C21 "C3216X7S2A225K160AB" 1206_180 1.65,-32.1 r180 bottom locked value=2.2uF
C22 "C3216X7S2A225K160AB" 1206_180 -4.1,-36.5 r90 bottom locked value=2.2uF
C23 "C3216X7S2A225K160AB" 1206_180 -1.8,-36.5 r90 bottom value=2.2uF
C24 "GRM155R61E104KA87D" 0402 -40.7,-29.9 r180 top locked value=0.1uF
C25 "885012206095" 0603 -15,-36.4 r180 top locked value=0.1uF
C26 "C0603X6S1C104K030BC" 0201_033 -13.75,-34.6 r90 bottom locked value=0.1uF
C27 "C0603X6S1C104K030BC" 0201_033 -18.5,-31 r0 bottom value=0.1uF
C28 "GRM155R71E222KA01D" 0402 -15.4,-34 r270 bottom value=2200pF
C29 "GRM155R61E104KA87D" 0402 -18.5,-35.2 r180 bottom value=0.1uF
C30 "GRM033R71E101JA01D" 0201_033 -18.5,-31.7 r180 bottom value=100pF
C31 "C2012X7S2A105K125AB" 0805_HV -7.2,-37.1 r270 bottom locked value=1uF
C32 "C0603X6S1C104K030BC" 0201_033 -24.8,-35.875 r0 bottom value=0.1uF
C33 "GRM155R61A105KE15D" 0402 -22.5,-37.625 r180 bottom value=1uF
C34 "C0603X6S1C104K030BC" 0201_033 -18.4,-13.1 r180 bottom value=0.1uF
C35 "C0603X6S1C104K030BC" 0201_033 -19.5,-11.8 r90 bottom value=0.1uF
C39 "GRM155R61E104KA87D" 0402 -75,-35 r180 top locked value=0.1uF
C40 "GRM155R61E104KA87D" 0402 -75,-33.4 r180 top locked value=0.1uF
C41 "GRM155R61E104KA87D" 0402 -69.3,-33.6 r180 bottom locked value=0.1uF
C42 "GRM155R61E104KA87D" 0402 -75,-30.4 r180 top locked value=0.1uF
C43 "GRM155R61E104KA87D" 0402 -69.3,-36.1 r180 bottom locked value=0.1uF
C47 "GRM188R61A475MAAJ" 0603 -69.2,-26.3 r90 top locked value=4.7uF
C50 "C1005X6S1C105K050BC" 0402 -65.6,-33.5 r90 bottom locked value=1uF
C51 "GRM155R61E104KA87D" 0402 -69.3,-34.9 r180 bottom locked value=0.1uF
C52 "GRM155R61E104KA87D" 0402 -68.3,-25.7 r180 bottom locked value=0.1uF
C53 "C0603X6S1C104K030BC" 0201_033 -0.77,-14.1 r0 top value=0.1uF
C54 "C0603X6S1C104K030BC" 0201_033 -0.8,-16.4 r0 top value=0.1uF
C55 "C0603X6S1C104K030BC" 0201_033 -0.8,-18.7 r0 top value=0.1uF
C56 "885012206095" 0603 -54.2,-17.6 r180 bottom locked value=0.1uF
C57 "885012206095" 0603 -5.3,-32.8 r90 top locked value=0.1uF
C58 "GRM21BR61A476ME15L" 0805_HV -57.9,-14.616 r90 bottom value=47uF
C59 "GRM21BR61A476ME15L" 0805_HV -57.9,-14.616 r90 top value=47uF
C60 "885012206095" 0603 -55.2,-16.2 r0 top locked value=0.1uF
C61 "C0603X6S1C104K030BC" 0201_033 -59.4,-14.7 r90 top value=0.1uF
C62 "GRM155R71H272KA01D" 0402 -53.5,-11.3 r90 bottom value=2700pF
C63 "GRM21BR61A476ME15L" 0805_HV -47.816,-17.725 r180 top value=47uF
C64 "GRM21BR61A476ME15L" 0805_HV -47.816,-15.525 r180 top value=47uF
C65 "885012206095" 0603 -47.6,-13.625 r180 top value=0.1uF
C66 "C0603X6S1C104K030BC" 0201_033 -60.1,-16 r180 top value=0.1uF
C67 "GRM155R71H272KA01D" 0402 -56,-11.3 r90 bottom locked value=2700pF
C68 "GRM155R61E104KA87D" 0402 -58.4,-11.3 r270 bottom locked value=0.1uF
C70 "885012206095" 0603 -51.6,-29 r180 bottom locked value=0.1uF
C71 "885012206095" 0603 -58.8,-35.8 r180 bottom locked value=0.1uF
C72 "GRM21BR61A476ME15L" 0805_HV -55.7,-26.184 r90 top value=47uF
C73 "885012206095" 0603 -53.8,-26.5 r90 top value=0.1uF
C74 "GRM21BR61A476ME15L" 0805_HV -55.2,-26.3 r90 bottom value=47uF
C75 "GRM21BR61A476ME15L" 0805_HV -62.4,-33 r90 top value=47uF
C76 "GRM21BR61A476ME15L" 0805_HV -62.4,-33 r90 bottom locked value=47uF
C77 "885012206095" 0603 -64.2,-33.2 r90 bottom locked value=0.1uF
C78 "GRM155R71H272KA01D" 0402 -50.7,-21.9 r90 bottom locked value=2700pF
C79 "GRM21BR61A476ME15L" 0805_HV -45.5,-24.6 r180 top locked value=47uF
C80 "GRM155R71H272KA01D" 0402 -58.1,-28.7 r90 bottom value=2700pF
C81 "GRM21BR61A476ME15L" 0805_HV -55.916,-33.9 r180 top value=47uF
C82 "GRM21BR61A476ME15L" 0805_HV -55.916,-31.7 r180 top value=47uF
C83 "885012206095" 0603 -56.1,-35.8 r0 top value=0.1uF
C84 "GRM21BR61A476ME15L" 0805_HV -45.5,-26.8 r180 top locked value=47uF
C85 "885012206095" 0603 -45.7,-28.7 r180 top locked value=0.1uF
C86 "GRM155R61E104KA87D" 0402 0.5,-34.7 r90 top locked value=0.1uF
C87 "GRM155R61E104KA87D" 0402 -2.3,-34.1 r90 top value=0.1uF
C88 "GRM155R71H272KA01D" 0402 -59.3,-28.7 r90 bottom value=2700pF
C90 "GRM155R71H272KA01D" 0402 -53.9,-22.5 r180 bottom locked value=2700pF
C91 "GRM155R61E104KA87D" 0402 -61.7,-29.7 r270 bottom locked value=0.1uF
C92 "GRM155R61E104KA87D" 0402 -53.9,-21.3 r180 bottom locked value=0.1uF
C94 "GRM155R61E104KA87D" 0402 -38.7,-15 r270 bottom value=0.1uF
C95 "GRM21BR61A476ME15L" 0805_HV -37,-17.9 r180 bottom locked value=47uF
C96 "GRM21BR61A476ME15L" 0805_HV -40.9,-17.9 r0 bottom locked value=47uF
C97 "GRM188R61A475MAAJ" 0603 -33.4,-16.8 r0 bottom locked value=4.7uF
C98 "GRM188R61C106MAALD" 0603 -30.2,-16.8 r180 bottom locked value=10uF
C99 "GRM21BR61A476ME15L" 0805_HV -28.5,-14.1 r90 bottom locked value=47uF
C100 "GRM21BR61A476ME15L" 0805_HV -32.9,-14.084 r90 bottom locked value=47uF
C101 "GRM21BR61A476ME15L" 0805_HV -30.7,-14.084 r90 bottom value=47uF
C102 "GRM188R61C106MAALD" 0603 -20.35,-14.58 r90 top value=10uF
C103 "GRM188R61C106MAALD" 0603 -18.75,-14.58 r90 top value=10uF
C104 "GRM033R71E101JA01D" 0201_033 -35.2,-11.17 r90 bottom value=100pF
C106 "GRM1555C1H100FA01D" 0402 -32.9,-11.5 r0 bottom locked value=10pF
C107 "885012206095" 0603 -11.35,-32.2 r90 top value=0.1uF
C108 "GRM155R61E104KA87D" 0402 -30.3,-11.5 r180 bottom locked value=0.1uF
C109 "885012206095" 0603 -27.95,-14.58 r90 top value=0.1uF
C110 "GRM188R61C106MAALD" 0603 -26.35,-14.58 r90 top locked value=10uF
C111 "885012205031" 0402 -16.6,-14.8 r90 top value=0.01uF
C112 "885012205031" 0402 -16.6,-17.4 r270 top value=0.01uF
C113 "GRM188R61C106MAALD" 0603 -26.35,-17.78 r270 top locked value=10uF
C114 "885012206095" 0603 -27.95,-17.78 r270 top value=0.1uF
C115 "GRM188R61C106MAALD" 0603 -18.75,-17.78 r90 top value=10uF
C116 "GRM188R61C106MAALD" 0603 -20.35,-17.78 r90 top value=10uF
C117 "885012206095" 0603 -17.6,-34.4 r90 top locked value=0.1uF
C118 "885012205031" 0402 -24.25,-13.58 r0 top value=0.01uF
C119 "885012005061" 0402 -27.7,-20.8 r270 bottom value=100pF
C120 "885012207026" 0805_HV -39.1,-21.3 r90 bottom locked value=10uF
C121 "885012207026" 0805_HV -41.3,-21.3 r90 bottom value=10uF
C122 "885012206095" 0603 -38,-24.3 r0 bottom value=0.1uF
C123 "GRM21BR61A476ME15L" 0805_HV -31.9,-21.5 r270 bottom locked value=47uF
C124 "885012206048" 0603 -41.4,-24.2 r180 top locked value=0.22uF
C125 "885012206095" 0603 -74.8,-22.7 r270 bottom value=0.1uF
C126 "GRM21BC81A106KE18L" 0805_HV -72.9,-22.384 r270 bottom locked value=10uF
C127 "GRM21BC81A106KE18L" 0805_HV -68.5,-22.4 r270 bottom locked value=10uF
C128 "GRM21BC81A106KE18L" 0805_HV -70.7,-22.384 r270 bottom value=10uF
C129 "GRM21BC81A106KE18L" 0805_HV -66.3,-22.384 r270 bottom locked value=10uF
C130 "885012206095" 0603 -64.4,-22.7 r270 bottom locked value=0.1uF
C131 "GRM21BR61A476ME15L" 0805_HV -57.9,-19.8 r0 bottom locked value=47uF
C132 "GRM21BR61A476ME15L" 0805_HV -57.9,-22 r0 bottom locked value=47uF
C133 "885012206095" 0603 -57.6,-17.9 r0 bottom value=0.1uF
C134 "GRM155R71E473KA88D" 0402 -65.4,-19.6 r90 top locked value=0.047uF
C135 "C0603X6S1C104K030BC" 0201_033 -62.1,-27.67 r90 top value=0.1uF
C136 "GRM155R71E682KA01D" 0402 -60.719,-24.7 r90 bottom value=6800pF
C137 "GRM155R61E104KA87D" 0402 -60.719,-24.7 r270 top value=0.1uF
C138 "C0603X6S1C104K030BC" 0201_033 -62.4,-24.6 r270 top value=0.1uF
C139 "GRM21BR61A476ME15L" 0805_HV -64.4,-12.8 r90 bottom locked value=47uF
C140 "GRM21BR61A476ME15L" 0805_HV -68.8,-12.8 r90 bottom locked value=47uF
C141 "GRM21BR61A476ME15L" 0805_HV -62.2,-12.8 r90 bottom locked value=47uF
C142 "GRM21BC81A106KE18L" 0805_HV -66.6,-12.8 r90 bottom locked value=10uF
C143 "885012206095" 0603 -60.4,-12.7 r90 bottom locked value=0.1uF
C144 "GRT188R61C475KE13D" 0603 -73,-19.3 r180 bottom locked value=4.7uF
C145 "GRM21BC81A106KE18L" 0805_HV -70.947,-12.789 r90 bottom locked value=10uF
C146 "GRM21BC81A106KE18L" 0805_HV -73.147,-12.789 r90 bottom locked value=10uF
C147 "GRM155R71E473KA88D" 0402 -65.4,-17 r270 top locked value=0.047uF
C148 "C0603X6S1C104K030BC" 0201_033 -61.6,-24.6 r270 top value=0.1uF
C149 "C0603C102F3GACTU" 0603 -66.8,-17.3 r90 top locked value=1000pF
C150 "885012206095" 0603 -7.75,-42.6 r270 bottom value=0.1uF
C151 "C0603X6S1C104K030BC" 0201_033 -7,-18.2 r0 top value=0.1uF
C152 "GRM155R61E104KA87D" 0402 -10.1,-6.7 r270 bottom value=0.1uF
C153 "GRM155R61E104KA87D" 0402 -1.8,-6.7 r270 bottom value=0.1uF
C154 "885012206095" 0603 -19.6,-17.6 r180 bottom value=0.1uF
C155 "885012206095" 0603 -15.3,-6.4 r90 bottom value=0.1uF
C157 "C0603X6S1C104K030BC" 0201_033 -5.7,-16.8 r0 top value=0.1uF
C169 "GRM188R61A475MAAJ" 0603 -18.4,-21.9 r270 top value=4.7uF
C171 "885012206095" 0603 -45.4,-38.4 r180 bottom locked value=0.1uF
C172 "885012206052" 0603 -26,-21.9 r270 top value=1uF
C173 "C1608X5R1A106M080AC" 0603 -27.5,-21.9 r270 top value=10uF
C174 "GRM21BR61A476ME15L" 0805_HV -49.2,-35.5 r90 bottom value=47uF
C175 "GRM21BR61A476ME15L" 0805_HV -49.3,-32.6 r90 top value=47uF
C176 "885012206095" 0603 -51.2,-32.2 r90 top value=0.1uF
C177 "GRM21BR61A476ME15L" 0805_HV -43.4,-32.1 r180 top locked value=47uF
C178 "GRM21BR61A476ME15L" 0805_HV -43.4,-34.3 r180 top locked value=47uF
C179 "GRM155R61E104KA87D" 0402 -43.6,-36 r180 top value=0.1uF
C180 "GRM155R61E104KA87D" 0402 -19.6,-22.2 r270 top value=0.1uF
C181 "C1608X5R1A106M080AC" 0603 -16.7,-21.9 r270 top value=10uF
C182 "GRM155R71H272KA01D" 0402 -42.6,-31.7 r90 bottom value=2700pF
C183 "885012206095" 0603 -9.7,-32.2 r90 top value=0.1uF
C184 "GRM188R61A475MAAJ" 0603 -18.6,-24.3 r0 top locked value=4.7uF
C185 "GRM1555C1E471JA01D" 0402 -27,-25.3 r180 top value=470pF
C186 "GRM155R71H272KA01D" 0402 -47.9,-31.7 r90 bottom locked value=2700pF
C187 "GRM155R61E104KA87D" 0402 -45.5,-31.7 r90 bottom value=0.1uF
C189 "885012206095" 0603 -32.8,-32.4 r270 bottom locked value=0.1uF
C190 "C1608X5R1A106M080AC" 0603 -18.8,-28.4 r270 top value=10uF
C191 "GRM155R61E104KA87D" 0402 -10.6,-14.3 r270 top locked value=0.1uF
C192 "GRM21BR61A476ME15L" 0805_HV -31.286,-35.919 r90 bottom locked value=47uF
C193 "GRM21BR61A476ME15L" 0805_HV -29.086,-35.919 r90 bottom locked value=47uF
C194 "885012206095" 0603 -33.1,-36 r90 bottom locked value=0.1uF
C195 "GRM21BR61A476ME15L" 0805_HV -30.7,-27.7 r270 bottom locked value=47uF
C196 "GRM21BR61A476ME15L" 0805_HV -32.9,-27.7 r270 bottom locked value=47uF
C197 "GRM155R61E104KA87D" 0402 -29,-27.2 r270 bottom locked value=0.1uF
C198 "GRM155R71H272KA01D" 0402 -38.8,-34.9 r270 bottom locked value=2700pF
C199 "C1608X5R1A106M080AC" 0603 -29.4,-28 r270 top locked value=10uF
C200 "GRM155R61E104KA87D" 0402 -30.8,-27.8 r270 top locked value=0.1uF
C201 "885012206052" 0603 -26.6,-33.4 r0 top value=1uF
C202 "GRM155R61E104KA87D" 0402 -20.2,-28.2 r270 top value=0.1uF
C203 "C1608X5R1A106M080AC" 0603 -21.6,-28.4 r270 top value=10uF
C204 "GRM155R61E104KA87D" 0402 3.4,-34.1 r90 top value=0.1uF
C205 "GRM155R61E104KA87D" 0402 -23.7,-33.2 r180 top locked value=0.1uF
C206 "GRM155R71H182KA01D" 0402 -39.3,-35.4 r180 top locked value=1800pF
C207 "GRM155R61E104KA87D" 0402 -39.3,-34 r180 top value=0.1uF
D1 "STPS1150A" SMA -5.25,-16.9 r180 bottom locked value=150V
D2 "STPS1150A" SMA -5.25,-32.5 r180 bottom locked value=150V
D3 "LTST-C193KGKT-5A" LTST-C193_Green -11.4,-33.1 r180 bottom value=Green
D4 "HSMC-C191" HSMx-C191_Red -53.9,-19.2 r180 bottom locked value=Red
D5 "HSMC-C191" HSMx-C191_Red -55.05,-29.1 r0 bottom locked value=Red
D6 "HSMC-C191" HSMx-C191_Red -63.2,-35.9 r0 bottom value=Red
D7 "HSMC-C191" HSMx-C191_Red -53.1,-34.75 r270 top value=Red
D8 "1N4148X-TP" SOD-523 -30.1,-21 r270 bottom value=75V
D9 "1N4148X-TP" SOD-523 -40.85,-23.9 r0 bottom locked value=75V
D10 "HSMA-C190" HSMx-C190_Amber -8.75,-17.6 r270 top locked value=Amber
D11 "ESD351DPYR" DPY0002A -2.7,-41.95 r270 bottom
D12 "ESD351DPYR" DPY0002A -3.7,-41.95 r270 bottom
D13 "SML-P12PTT86" SML-P1_GREEN -70.1,-20.7 r180 top value=Green
D14 "HSMC-C191" HSMx-C191_Red -28.1,-33.2 r180 bottom locked value=Red
D15 "HSMC-C191" HSMx-C191_Red -29.4,-31.45 r90 top value=Red
D16 "HSMC-C191" HSMx-C191_Red -23.8,-25.5 r180 top locked value=Red
D17 "HSMC-C191" HSMx-C191_Red -37.4,-19.2 r270 top locked value=Red
J2 "801-41-003-10-001000" Mill-Max_801-41-003-10-001000 -76.2,-18.4 r270 top locked
L1 "74404084101" WE-LQS_8040 -13.8,-24 r270 bottom locked value=100uH
L2 "74479776233" WE-PMI_0806HS 0.8,-11.7 r180 bottom value=3.3uH
L3 "744043102" WE-TPC_4828 -4.25,-21.25 r90 bottom locked value=1mH
L4 "BLM18BD252SN1D" 0603 -12.65,-11.6 r90 bottom locked value="2500 ohm"
L5 "744043102" WE-TPC_4828 -4.3,-27.6 r180 bottom value=1mH
L6 "BLM18BD252SN1D" 0603 -14.2,-37.2 r270 bottom locked value="2500 ohm"
L7 "74479776233" WE-PMI_0806HS 0.65,-34.1 r180 bottom value=3.3uH
L8 "BLM18HE152SN1D" 0603 -68.4,-27.1 r0 bottom locked value="1500 ohm"
L9 "BLM18HE152SN1D" 0603 -66.4,-35.9 r180 bottom locked value="1500 ohm"
L10 "744053330" WE-TPC-LH -49,-13.8 r0 bottom locked value=33uH
L11 "BLM18SG221TN1D" 0603 -6.8,-32.8 r270 top value="220 ohm"
L12 "744053330" WE-TPC-LH -46.5,-24.8 r0 bottom locked value=33uH
L13 "BLM18SG221TN1D" 0603 -3.7,-34.4 r270 top value="220 ohm"
L14 "NRS5030T6R8MMGJV" NRS5030 -54.3,-33.3 r0 bottom locked value=6.8uH
L15 "BLM18SG121TN1D" 0603 -0.9,-34.4 r270 top value="120 ohm"
L16 "IHLP2020CZER150M01" IHLP-2020CZ -42.1,-13.7 r90 bottom locked value=15uH
L17 "BLM18BD252SN1D" 0603 -13,-32.4 r270 top locked value="2500 ohm"
L18 "BLM18BD252SN1D" 0603 -19.2,-34.4 r270 top value="2500 ohm"
L19 "VLCF5020T-2R2N2R6-3" VLCF5020 -62.6,-18.175 r270 bottom locked value=2.2uH
L20 "742792609" 0603 -8.7,-6.4 r270 bottom value="30 ohm"
L21 "742792609" 0603 -3.2,-6.4 r270 bottom value="30 ohm"
L22 "742792609" 0603 -15.1,-14.6 r90 top locked value="30 ohm"
L23 "VLCF4020T-2R2N1R7" VLCF4020 -41.7,-35.8 r0 bottom locked value=2.2uH
L24 "742792609" 0603 -19.6,-19.15 r0 bottom value="30 ohm"
L25 "BLM18SG221TN1D" 0603 -12,-14.6 r90 top locked value="220 ohm"
L26 "744062002" WE-TPC_6823 -37.7,-29.3 r0 bottom locked value=2.2uH
L27 "BLM18SG221TN1D" 0603 1.9,-34.4 r270 top locked value="220 ohm"
L28 "742792609" 0603 -16.85,-6.4 r270 bottom value="30 ohm"
L29 "742792609" 0603 -6.2,-42.6 r90 bottom value="30 ohm"
Logo1 "CE Mark" TI_Stacked_Overlay_Small -6.7,-27.25 r0 top (schematic designator LOGO1)
Logo2 "DANGER HIGH VOLTAGE" CE_Mark_5mm -0.45,-23.8 r0 top (schematic designator LOGO2)
Logo3 "Pb-Free Symbol" FCC_disclaimer 23.6,15.35 r90 top
Logo5 "WEEE logo" WEEE_Minimum -33.2,-17.25 r0 top
MP1 "6508128-030" 0-MFG -78,-14.05 r90 bottom
MP2 "6508128-030" 0-MFG -78,-24.05 r90 bottom locked
MP3 "6508128-030" 0-MFG -78,-34.95 r270 bottom locked
MP4 "6508128-030" 0-MFG -71.95,-40 r0 bottom locked
MP5 "6508128-030" 0-MFG -61.95,-40 r0 bottom locked
MP6 "6508128-030" 0-MFG -51.95,-40 r0 bottom locked
MP7 "6508128-030" 0-MFG -41.95,-40 r0 bottom
MP8 "6508128-030" 0-MFG -31.95,-40 r0 bottom locked
MP9 "6508128-030" 0-MFG -21.95,-40 r0 bottom locked
MP10 "6508128-030" 0-MFG -11.95,-40 r0 bottom locked
MP11 "6508128-030" 0-MFG -1.95,-40 r180 bottom locked
MP12 "6508128-030" 0-MFG 5,-34.95 r90 bottom locked
MP13 "6508128-030" 0-MFG 5,-24.95 r270 bottom locked
MP14 "6508128-030" 0-MFG 5,-14.95 r270 bottom locked
MP15 "6508128-030" 0-MFG -1.95,-9 r0 bottom locked
MP16 "6508128-030" 0-MFG -11.95,-9 r0 bottom locked
MP17 "6508128-030" 0-MFG -21.95,-9 r0 bottom locked
MP18 "6508128-030" 0-MFG -31.95,-9 r0 bottom locked
MP19 "6508128-030" 0-MFG -41.95,-9 r0 bottom locked
MP20 "6508128-030" 0-MFG -51.95,-9 r0 bottom locked
MP21 "6508128-030" 0-MFG -61.95,-9 r180 bottom locked
MP22 "6508128-030" 0-MFG -71.95,-9 r180 bottom locked
MP23 "6508128-030" 0-MFG -78,-14.05 r90 top locked
MP24 "6508128-030" 0-MFG -78,-24.05 r90 top locked
MP25 "6508128-030" 0-MFG -78,-34.95 r90 top
MP26 "6508128-030" 0-MFG -71.95,-40 r180 top locked
MP27 "6508128-030" 0-MFG -61.95,-40 r180 top locked
MP28 "6508128-030" 0-MFG -51.95,-40 r180 top locked
MP29 "6508128-030" 0-MFG -41.95,-40 r180 top locked
MP30 "6508128-030" 0-MFG -32.95,-40 r180 top locked
MP31 "6508128-030" 0-MFG -23.95,-40 r180 top locked
MP32 "6508128-030" 0-MFG 5,-32.55 r90 top locked
MP33 "6508128-030" 0-MFG 5,-24.45 r90 top locked
MP34 "6508128-030" 0-MFG 5,-16.45 r270 top locked
MP35 "6508128-030" 0-MFG -23.95,-9 r180 top locked
MP36 "6508128-030" 0-MFG -32.95,-9 r180 top locked
MP37 "6508128-030" 0-MFG -41.95,-9 r180 top locked
MP38 "6508128-030" 0-MFG -51.95,-9 r0 top locked
MP39 "6508128-030" 0-MFG -61.95,-9 r180 top locked
MP40 "6508128-030" 0-MFG -71.95,-9 r180 top locked
P1 "AXK5S80347YG" Panasonic_AXK5S80347Y -6.671,-41.464 r180 top locked
P2 "AXK5S80347YG" Panasonic_AXK5S80347Y -6.671,-7.238 r180 top locked
Q1 "FMMT495TA" SOT-23 -10.2,-11.7 r90 bottom locked value="150 V"
Q2 "FMMT596TA" SOT-23 -11.5,-37.45 r0 bottom value="200 V"
Q3 "CSD15380F3" YJM0003A -10.85,-34.8 r270 bottom locked value=20V
R1 "RK73H1ETTP1002F" 0402 -7.2,-10.7 r0 bottom locked value=10.0k
R2 "RC0805JR-070RL" 0805_HV -15.9,-18.6 r0 bottom locked value=0
R3 "RC0805JR-070RL" 0805_HV -16,-15.8 r0 bottom locked value=0
R4 "RC0603FR-0768K1L" 0603 -0.75,-14.1 r90 bottom locked value=68.1k
R5 "RC0201FR-0753K6L" 0201 -14.45,-34.6 r270 bottom locked value=53.6k
R6 "CRCW0603100KJNEAC" 0603 2.45,-14.1 r90 bottom value=100k
R7 "RC0603FR-0759KL" 0603 0.85,-14.1 r270 bottom locked value=59.0k
R8 "RC0201FR-7D1KL" 0201 -13.75,-33.3 r270 bottom value=1.00k
R9 "CRCW040284K5FKED" 0402 -35.9,-25.9 r90 top locked value=84.5k
R10 "CRCW0402523RFKED" 0402 -9.42,-32.33 r270 bottom value=523
R11 "CRCW04023K83FKED" 0402 -19,-33.3 r90 bottom value=3.83k
R12 "CRCW02010000Z0ED" 0201 -12.35,-34.6 r90 bottom value=0
R13 "RC0603FR-07162KL" 0603 -19,-37.4 r90 bottom value=162k
R14 "CRCW0603100KJNEAC" 0603 1.4,-37.4 r270 bottom value=100k
R15 "RC0201FR-0761K9L" 0201 -13.05,-34.6 r90 bottom value=61.9k
R16 "CRCW02010000Z0ED" 0201 -70.2,-19.1 r0 top value=0
R17 "RC0201FR-0737K4L" 0201 -18.5,-30 r0 bottom value=37.4k
R18 "RC0201FR-0786K6L" 0201 -14.4,-32.73 r90 bottom value=86.6k
R19 "CRCW040211K3FKED" 0402 -16.6,-34 r90 bottom value=11.3k
R20 "RC0603FR-07162KL" 0603 -17.4,-37.4 r90 bottom locked value=162k
R21 "RC0201FR-7D1KL" 0201 -11.65,-34.6 r90 bottom value=1.00k
R23 "RK73H1ETTP1002F" 0402 -9,-37.7 r90 bottom value=10.0k
R24 "CRCW02010000Z0ED" 0201 -22.85,-34 r0 bottom value=0
R25 "RC0201FS-7D10KL" 0201 -21.4,-34 r180 bottom value=10.0k
R26 "RC0201FS-7D10KL" 0201 -20.6,-35.875 r180 bottom value=10.0k
R27 "RC0201FS-7D10KL" 0201 -20.6,-35.175 r180 bottom value=10.0k
R28 "WSLP0805R0200FEB" WSLP0805 -22.151,-11.869 r270 bottom value=0.02
R30 "RC0201FR-7D10RL" 0201 -20.6,-11.4 r180 bottom value=10.0
R31 "RC0201FR-7D10RL" 0201 -20.6,-12.2 r180 bottom value=10.0
R32 "RC0201FS-7D10KL" 0201 -17.081,-13.019 r0 bottom value=10.0k
R33 "RC0201FS-7D10KL" 0201 -16.681,-12.019 r270 bottom value=10.0k
R37 "CRCW02010000Z0ED" 0201 -71.45,-28.1 r0 top value=0
R38 "RC0201FS-7D10KL" 0201 -68.7,-30.9 r0 bottom value=10.0k
R39 "RC0201FS-7D10KL" 0201 -68.7,-28.8 r0 bottom value=10.0k
R40 "CRCW02010000Z0ED" 0201 -68.7,-28.1 r0 top value=0
R41 "CRCW02010000Z0ED" 0201 -74.6,-31.3 r180 top value=0
R42 "CRCW02010000Z0ED" 0201 -3.4,-13.5 r0 top value=0
R43 "CRCW02010000Z0ED" 0201 -3,-14.9 r90 top value=0
R44 "CRCW02010000Z0ED" 0201 -68.7,-30.3 r180 bottom value=0
R45 "CRCW02010000Z0ED" 0201 -68.7,-29.4 r180 bottom value=0
R46 "CRCW02010000Z0ED" 0201 -0.77,-13.5 r180 top value=0
R47 "RC0201FR-0718RL" 0201 -71.4,-36.5 r180 bottom value=18.0
R48 "CRCW02010000Z0ED" 0201 -74.57,-29.6 r180 top value=0
R49 "CRCW02010000Z0ED" 0201 -74.6,-32.05 r180 top value=0
R50 "RC0201FR-0718RL" 0201 -74.6,-35.8 r0 top value=18.0
R51 "CRCW02010000Z0ED" 0201 -3.6,-17 r0 top value=0
R53 "RC0201FR-0718RL" 0201 -65.47,-34.2 r180 top value=18.0
R54 "CRCW02010000Z0ED" 0201 -0.8,-15.8 r180 top value=0
R55 "RC0201FR-0718RL" 0201 -71.3,-33.9 r180 bottom value=18.0
R56 "RC0201FR-0718RL" 0201 -71.3,-33.1 r180 bottom value=18.0
R57 "RC0201FR-0718RL" 0201 -65.53,-33 r180 top value=18.0
R58 "RC0201FR-0718RL" 0201 -65.6,-32.3 r180 top value=18.0
R59 "RC0201FR-0718RL" 0201 -65.8,-30.6 r270 top value=18.0
R60 "CRCW02010000Z0ED" 0201 -3.63,-19.2 r0 top value=0
R61 "CRCW02010000Z0ED" 0201 -0.8,-18 r180 top value=0
R62 "CRCW040284K5FKED" 0402 -37.9,-31.1 r180 top value=84.5k
R63 "CRCW040284K5FKED" 0402 -37.9,-29.9 r180 top value=84.5k
R64 "CRCW0402523RFKED" 0402 -51.3,-19.2 r180 bottom value=523
R66 "WSLP0805R0200FEB" WSLP0805 -59.56,-19.8 r180 top locked value=0.02
R67 "RC0805JR-070RL" 0805_HV -56.984,-18.1 r0 top locked value=0
R68 "RC0201FR-0721K5L" 0201 -49.8,-14.225 r0 top value=21.5k
R70 "RC0201FR-7D10RL" 0201 -59.7,-17.2 r270 top value=10.0
R71 "RC0201FR-7D10RL" 0201 -60.5,-17.2 r270 top value=10.0
R72 "RC0201FS-7D10KL" 0201 -60.2,-13 r90 top value=10.0k
R73 "RC0201FS-7D10KL" 0201 -60.9,-13 r90 top value=10.0k
R74 "RC0201FS-7D10KL" 0201 -50.1,-15.2 r90 top value=10.0k
R75 "RC0201FR-07383KL" 0201 -55.1,-11 r90 bottom value=383k
R76 "CRCW0402160RJNED" 0402 -57.2,-11.3 r270 bottom locked value=160
R77 "CRCW0402523RFKED" 0402 -56.9,-27.7 r270 bottom value=523
R78 "CRCW0402523RFKED" 0402 -63.3,-35.9 r180 top value=523
R81 "RC0805JR-070RL" 0805_HV -58.8,-27.1 r0 top locked value=0
R82 "RC0805JR-070RL" 0805_HV -63.1,-29.4 r180 top value=0
R83 "RC0201FR-0712K4L" 0201 -58.4,-29.7 r0 top value=12.4k
R84 "RC0201FR-7D2K49L" 0201 -52.7,-23.5 r0 bottom value=2.49k
R85 "RC0201FS-7D10KL" 0201 -60.1,-29.7 r0 top value=10.0k
R86 "RC0201FR-07383KL" 0201 -56.2,-30.3 r0 bottom value=383k
R87 "RC0201FS-7D10KL" 0201 -54.2,-23.5 r0 bottom value=10.0k
R88 "RC0201FR-07383KL" 0201 -51,-22.47 r90 top value=383k
R89 "CRCW0402160RJNED" 0402 -60.5,-28.7 r270 bottom value=160
R90 "CRCW0402160RJNED" 0402 -52,-21.9 r270 bottom locked value=160
R91 "RC0805JR-070RL" 0805_HV -42.884,-17.9 r0 top value=0
R92 "RC0201FR-7D10KL" 0201 -34,-18.2 r90 bottom value=10.0k
R93 "RC0603JR-070RL" 0603 -25.8,-15.3 r0 bottom locked value=0
R94 "CRCW02010000Z0ED" 0201 -34.7,-18.2 r90 bottom value=0
R95 "RC0201FS-7D301KL" 0201 -34.5,-11.1 r90 bottom value=301k
R96 "RC0201FR-07475KL" 0201 -37.3,-11.17 r270 bottom value=475k
R97 "RC0201FR-07374KL" 0201 -36.6,-11.17 r270 bottom value=374k
R98 "RC0201FR-0786K6L" 0201 -35.9,-11.17 r270 bottom value=86.6k
R99 "RC0201FR-071K8L" 0201 -33.1,-10.7 r180 bottom value=1.80k
R100 "RC0201FR-7D10KL" 0201 -17.6,-13.9 r270 top value=10.0k
R101 "RC0201FR-0732K4L" 0201 -17.6,-15.27 r270 top value=32.4k
R102 "RC0201FR-0742K2L" 0201 -17.6,-16.9 r270 top value=42.2k
R103 "RC0201FR-7D10KL" 0201 -17.6,-18.3 r270 top value=10.0k
R104 "RC0603JR-070RL" 0603 -41.3,-21.4 r270 top locked value=0
R105 "RC0603JR-070RL" 0603 -43.9,-21.4 r270 top locked value=0
R106 "CRCW02010000Z0ED" 0201 -40.3,-24.9 r0 bottom value=0
R107 "CRCW0402110KJNED" 0402 -28.9,-20.8 r90 bottom value=110k
R108 "CRCW02010000Z0ED" 0201 -36.6,-19.4 r180 bottom value=0
R109 "RC0201FR-0726K1L" 0201 -29.7,-22.8 r0 bottom value=26.1k
R110 "CRCW02010000Z0ED" 0201 -35.1,-19.4 r180 bottom value=0
R111 "CRCW02010000Z0ED" 0201 -42.5,-25.73 r90 top value=0
R112 "RC0402FR-071KL" 0402 -38.3,-24.3 r0 top locked value=1.00k
R113 "RC0603JR-070RL" 0603 -31.1,-24.2 r0 bottom locked value=0
R116 "WSLP0805R0200FEB" WSLP0805 -5.6,-14.2 r0 top locked value=0.02
R117 "RC0805JR-070RL" 0805_HV -70,-14 r0 top locked value=0
R118 "CRCW0402475RFKED" 0402 -8.1,-15.6 r0 top locked value=475
R121 "RC0201FR-0735K7L" 0201 -57.9,-23.1 r180 top locked value=35.7k
R122 "RC0201FS-7D10KL" 0201 -57.8,-25.3 r0 top value=10.0k
R123 "RC0201FS-7D10KL" 0201 -65.2,-26.93 r270 top value=10.0k
R124 "RC0201FS-7D10KL" 0201 -62.9,-27.63 r90 top value=10.0k
R125 "RC0201FS-7D10KL" 0201 -57.8,-24.6 r0 top value=10.0k
R126 "RC0201FR-7D4K7L" 0201 -67.7,-14.5 r90 top value=4.70k
R127 "RC0201FS-7D10KL" 0201 -56.4,-23.5 r270 top value=10.0k
R128 "RC0201FR-07127KL" 0201 -67.5,-20.8 r90 top value=127k
R129 "CRCW0402549RFKED" 0402 -59.519,-24.7 r90 top value=549
R130 "RC0201FR-7D100KL" 0201 -67.5,-22.7 r270 top value=100k
R131 "RC0201FS-7D10KL" 0201 -62,-22.9 r270 top value=10.0k
R132 "CRCW02010000Z0ED" 0201 -62.5,-26.6 r180 top value=0
R133 "CRCW0402475RFKED" 0402 -72.2,-20 r90 top locked value=475
R134 "CRCW0402100RJNED" 0402 -73.3,-15.4 r180 bottom locked value=100
R135 "CRCW0402100RJNED" 0402 -73.3,-16.6 r180 bottom locked value=100
R136 "RC0201FR-075K23L" 0201 -70.2,-17.7 r180 bottom value=5.23k
R137 "RC0201FR-0730K1L" 0201 -70.2,-17 r0 bottom locked value=30.1k
R138 "RC0201FS-7D10KL" 0201 -70.2,-18.4 r0 top value=10.0k
R139 "RC0201FS-7D10KL" 0201 -70.2,-18.4 r0 bottom locked value=10.0k
R140 "RC0201FS-7D10KL" 0201 -73.5,-19 r90 top value=10.0k
R141 "RC0201FS-7D10KL" 0201 -73.2,-18.1 r0 bottom value=10.0k
R142 "RC0201FS-7D10KL" 0201 -70.2,-17 r0 top value=10.0k
R143 "RC0201FS-7D10KL" 0201 -70.2,-19.8 r0 top value=10.0k
R144 "RC0201FS-7D10KL" 0201 -72.2,-17.2 r0 top value=10.0k
R145 "RC0201FR-7D10RL" 0201 -5.15,-15.765 r90 top value=10.0
R146 "RC0201FR-7D10RL" 0201 -5.95,-15.765 r90 top value=10.0
R147 "CRCW02010000Z0ED" 0201 -7.3,-17.15 r270 top value=0
R148 "RC0201FS-7D10KL" 0201 -7,-20 r180 top value=10.0k
R149 "RC0201FS-7D10KL" 0201 -7,-19.2 r180 top value=10.0k
R150 "RC0603JR-070RL" 0603 -21.1,-15.3 r0 bottom locked value=0
R151 "CRCW04021K00FKED" 0402 -38.3,-17.3 r180 top value=1.00k
R152 "RC0603JR-070RL" 0603 -27.1,-17 r0 bottom locked value=0
R153 "RC0805JR-070RL" 0805_HV -23.216,-19.1 r0 top locked value=0
R154 "RC0805JR-070RL" 0805_HV -26.4,-26.3 r0 bottom locked value=0
R160 "CRCW0402523RFKED" 0402 -53.1,-31.9 r270 top value=523
R161 "CRCW02010000Z0ED" 0201 -48.7,-38.2 r270 bottom value=0
R162 "CRCW02010000Z0ED" 0201 -48,-38.2 r270 bottom value=0
R163 "RC0805JR-070RL" 0805_HV -50.3,-35.7 r0 top value=0
R164 "CRCW04021K00FKED" 0402 -21.2,-25.7 r0 top value=1.00k
R165 "CRCW040217K8FKED" 0402 -49.1,-31.7 r90 bottom locked value=17.8k
R166 "CRCW04022K49FKED" 0402 -28.9,-21.6 r90 top value=2.49k
R167 "CRCW040284K5FKED" 0402 -24.4,-24.1 r0 top locked value=84.5k
R168 "RC0201FS-7D10KL" 0201 -50,-31.97 r270 bottom value=10.0k
R169 "CRCW0402383KFKED" 0402 -44.3,-31.7 r90 bottom value=383k
R170 "CRCW040212K7FKED" 0402 -27,-24.1 r0 top value=12.7k
R171 "CRCW0402160RJNED" 0402 -46.7,-31.7 r270 bottom value=160
R172 "CRCW0402523RFKED" 0402 -27.3,-36.5 r90 bottom value=523
R173 "CRCW02010000Z0ED" 0201 -35.4,-38.2 r0 bottom value=0
R174 "CRCW02010000Z0ED" 0201 -33.8,-38.2 r180 bottom value=0
R175 "RC0805JR-070RL" 0805_HV -33.4,-33.1 r180 top locked value=0
R176 "CRCW04022K74FKED" 0402 -29.5,-33.6 r180 top locked value=2.74k
R177 "RC0201FR-077K5L" 0201 -38.5,-38.2 r180 bottom value=7.50k
R179 "CRCW04022K21FKED" 0402 -21.8,-31.3 r90 top value=2.21k
R180 "RC0201FS-7D10KL" 0201 -36.9,-38.2 r180 bottom value=10.0k
R181 "RC0201FR-07383KL" 0201 -38.5,-36.5 r180 bottom value=383k
R182 "CRCW04024K99FKED" 0402 -20.6,-31.3 r270 top value=4.99k
R183 "CRCW0402150RJNED" 0402 -37.4,-34.7 r270 top value=220
R184 "RC0201FS-7D10KL" 0201 -28.8,-23.6 r90 top value=10.0k
R185 "CRCW040212K0FKED" 0402 -21.5,-24.1 r0 top value=12.0k
R186 "CRCW02010000Z0ED" 0201 -45.2,-30.15 r180 bottom value=0
R187 "CRCW02010000Z0ED" 0201 -38.53,-37.2 r180 bottom value=0
R189 "CRCW02010000Z0ED" 0201 -54.4,-11 r90 bottom value=0
R190 "CRCW02010000Z0ED" 0201 -50.1,-22.47 r90 top value=0
R191 "CRCW02010000Z0ED" 0201 -57.2,-29.97 r90 bottom value=0
R192 "CRCW02010000Z0ED" 0201 -38.3,-11.5 r0 bottom value=0
R193 "CRCW02010000Z0ED" 0201 -70.2,-19.1 r0 bottom locked value=0
R194 "HCJ0805ZT0R00" FP-HCJ0805ZT0R00_0805-MFG 0.2,-6.2 r270 bottom locked value=0
R195 "RC0603JR-070RL" 0603 -22.6,-32.75 r0 bottom value=0
S1 "434153017835" SW_434153017835 -63.775,-26.575 r180 bottom locked
SCL "TESTPOINT" TESTPOINT -75.4,-28.3 r0 top
SDA "TESTPOINT" TESTPOINT -75.3,-26 r0 top
U1 "LM5158RTER" RTE0016K-MFG -15.8,-30.7 r180 bottom locked
U2 "DAC53401DSGR" DSG0008A-MFG -22.75,-35.425 r180 bottom locked
U3 "INA231AIYFFR" YFF0012AKAD -17.981,-11.919 r90 bottom locked
U5 "CDCE949PWR" PW0024A_N -69.95,-32.625 r0 top locked
U6 "SN74LVC1G11DRYR" DRY0006A#1 -2.1,-14 r0 top
U7 "SN74LVC1G11DRYR" DRY0006A#1 -2.2,-16.4 r0 top
U8 "SN74LVC1G11DRYR" DRY0006A#1 -2.2,-18.7 r0 top
U9 "LM3880MF-1AA" DBV0006A_N -38.725,-27.6 r0 top locked
U11 "TPS54218RTER" RTE0016F#1 -54.75,-14.6 r0 bottom locked
U12 "INA231AIYFFR" YFF0012AKAD -60.39,-14.6 r0 top
U13 "TPS54218RTER" RTE0016F#2 -52.2,-26.25 r0 bottom locked
U14 "TPS54218RTER" RTE0016F#1 -59.2,-32.8 r0 bottom locked
U15 "TPS61178RNWR" RNW0013A -36.3,-14 r270 bottom locked
U16 "TPS7A3901DSCR" DSC0010J -23.45,-16.28 r0 top locked
U17 "LMZM23601SILR" SIL0010A -35.5,-21.7 r0 bottom locked
U18 "BQ25790YBG" PREYBG0056 -67.4,-18.3 r90 bottom locked
U19 "TPS259470ARPW" RPW0010A -58.519,-24.6 r180 bottom locked
U20 "SN74LVC1G74DQER" DQE0008A -63.55,-23.925 r0 top
U21 "TPS3422EGDRYR" DRY0006A#2 -63.9,-26.8 r0 top
U23 "INA231AIYFFR" YFF0012AKAD -5.45,-17.965 r180 top locked
U25 "TPS54218RTER" RTE0016F#1 -46.25,-35.5 r0 bottom locked
U26 "TPS7A9601DSCR" DRC0010J-MFG -22.6,-21.8 r0 top locked
U27 "TPS54318RTER" RTE0016F#1 -35.8,-35.7 r90 bottom
U28 "TPS74401RGWR" RGW0020A -25.5,-29.3 r270 top locked
ZZ1 "This Assembly Note is for PCB labels only" AssemblyNoteLabel -103.606,63.952 r0 top
ZZ2 "These assemblies are ESD sensitive, ESD precautions shall be observed." AssemblyNote -92.43,71.572 r0 top
ZZ3 "These assemblies must be clean and free from flux and all contaminants. Use of no clean flux is not acceptable." AssemblyNote -96.24,90.622 r0 top
ZZ4 "These assemblies must comply with workmanship standards IPC-A-610 Class 2, unless otherwise specified." AssemblyNote -95.732,81.986 r0 top

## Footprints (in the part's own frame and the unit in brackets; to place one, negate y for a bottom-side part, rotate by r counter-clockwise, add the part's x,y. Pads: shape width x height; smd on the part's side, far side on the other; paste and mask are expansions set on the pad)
0-MFG [mm]
  rrect17% 0.6x0.9 smd paste+0 mask+0: 1(-3.05,0) 1(3.05,0)
  rrect11% 1.5x0.9 smd paste+0 mask+0: 1(-1.65,0) 1(1.65,0)
  rrect11% 1.2x0.9 smd paste+0 mask+0: 1(0,0)
  silkscreen extent -3.32,-0.82 3.32,0.82, body extent -3.25,-0.46 3.25,0.46, height 1.38
0201 [mm] "Data from Kemet datasheet CC101_COM dated 7/28/11"
  rect 0.46x0.42 smd mask+0.048: 1(-0.33,0) 2(0.33,0)
  body extent -0.31,-0.16 0.31,0.16, height 0.26
0201_033 [mm] "SMD, 2-Leads, Height 0.33mm"
  rect 0.46x0.42 smd mask+0.048: 1(-0.33,0) 2(0.33,0)
  body extent -0.31,-0.16 0.31,0.16, height 0.33
0402 [mm] "0402 from SM-752 data"
  rect 0.8x0.6 smd: 1(-0.6,0) 2(0.6,0)
  silkscreen extent -1.22,-0.52 1.22,0.52, body extent -0.55,-0.3 0.55,0.3, height 0.6
0603 [mm] "0603 from SM-752 data"
  rect 1x0.95 smd: 1(-0.8,0) 2(0.8,0)
  silkscreen extent -1.52,-0.69 1.52,0.69, body extent -0.87,-0.47 0.87,0.47, height 1
0805_HV [mil] "0805 with 30mil clearance between pads"
  rect 50x63 smd: 1(-40,0) 2(40,0)
  silkscreen extent -74,-40 74,40, body extent -43,-29 43,29, height 57
1206_180 [mm] "1206_180"
  rect 1.1x1.6 smd: 1(-1.7,0) 2(1.7,0)
  silkscreen extent -0.9,-1 0.9,1, body extent -1.75,-0.95 1.75,0.95, height 1.8
AssemblyNote [mm] "Assembly Note"
AssemblyNoteLabel [mm] "Assembly Note for PCB Labels"
CE_Mark_5mm [mm] "Minimum text height for CE Mark"
  silkscreen extent -3.5,-2.5 3.5,2.5
DBV0006A_N [mm] "SOT23, 6-Leads, Body 2.9x1.6mm, Pitch 0.95mm, Lead Span 2.8mm, IPC Medium Density"
  rrect17% 1x0.6 smd: 1(-1.375,0.95) 2(-1.375,0) 3(-1.375,-0.95) 4(1.375,-0.95) 5(1.375,0) 6(1.375,0.95)
  silkscreen extent -1.68,-1.55 0.5,1.55, body extent -1.42,-1.46 1.42,1.46, height 1.12
DPY0002A [mm] "X1SON-2"
  rrect57% 0.35x0.6 smd paste-0.5 mask-0.05: 1(-0.325,0) 2(0.325,0)
  rrect33% 0.3x0.5 on Bottom Paste: 1S(-0.35,0) 2S(0.35,0)
  silkscreen extent -0.85,-0.03 -0.8,0.02, body extent -0.5,-0.3 0.5,0.3, height 0.45
DQE0008A [mm] "SON, 8-Leads, Body 1.4x1mm, Pitch 0.35mm, TI Recommended"
  rect 0.6x0.16 smd: 1(-0.4,0.525)
  rect 0.5x0.16 smd: 2(-0.45,0.175) 3(-0.45,-0.175) 4(-0.45,-0.525) 5(0.45,-0.525) 6(0.45,-0.175) 7(0.45,0.175) 8(0.45,0.525)
  silkscreen extent -0.7,-0.85 0.4,0.85, body extent -0.53,-0.72 0.53,0.73, height 0.41
DRC0010J-MFG [mm]
  rrect42% 0.6x0.24 smd paste+0 mask+0: 1(-1.4,1) 2(-1.4,0.5) 3(-1.4,0) 4(-1.4,-0.5) 5(-1.4,-1) 6(1.4,-1) 7(1.4,-0.5) 8(1.4,0) 9(1.4,0.5) 10(1.4,1)
  round 1.485 smd paste-1000 mask+0: 11(0,0)
  Top Layer region: -0.825,-1.15 -0.818,-1.175 -0.8,-1.193 -0.775,-1.2 -0.775,-1.2 -0.375,-1.2 -0.375,-1.65 -0.368,-1.675 -0.35,-1.693 -0.325,-1.7 -0.325,-1.7 -0.175,-1.7 -0.156,-1.696 -0.14,-1.685 -0.129,-1.669 -0.125,-1.65 -0.125,-1.65 -0.125,-1.2 0.125,-1.2 0.125,-1.65 0.129,-1.669 0.14,-1.685 0.156,-1.696 0.175,-1.7 0.175,-1.7 0.325,-1.7 0.35,-1.693 0.368,-1.675 0.375,-1.65 0.375,-1.65 0.375,-1.2 0.775,-1.2 0.8,-1.193 0.818,-1.175 0.825,-1.15 0.825,-1.15 0.825,1.15 0.818,1.175 0.8,1.193 0.775,1.2 0.775,1.2 0.375,1.2 0.375,1.65 0.368,1.675 0.35,1.693 0.325,1.7 0.325,1.7 0.175,1.7 0.156,1.696 0.14,1.685 0.129,1.669 0.125,1.65 0.125,1.65 0.125,1.2 -0.125,1.2 -0.125,1.65 -0.129,1.669 -0.14,1.685 -0.156,1.696 -0.175,1.7 -0.175,1.7 -0.325,1.7 -0.35,1.693 -0.368,1.675 -0.375,1.65 -0.375,1.65 -0.375,1.2 -0.775,1.2 -0.8,1.193 -0.818,1.175 -0.825,1.15 -0.825,1.15
  silkscreen extent -2.37,-1.55 1.55,1.55, body extent -1.8,-1.8 1.8,1.8, height 0.25
DRY0006A#1 [mm] "USON-6"
  rrect67% 0.45x0.3 smd paste-0.05 mask-0.05: 1(-0.275,0.5)
  rrect67% 0.4x0.3 smd paste-0.05 mask-0.05: 2(-0.3,0) 3(-0.3,-0.5) 4(0.3,-0.5) 5(0.3,0) 6(0.3,0.5)
  body extent -0.5,-0.72 0.5,0.72, height 0.58
DRY0006A#2 [mm] "PSON, 6-Leads, Body 1x1.45mm, Pitch 0.5mm, TI Recommended"
  rect 0.35x0.2 smd: 1(-0.275,0.5)
  rect 0.3x0.2 smd: 2(-0.3,0) 3(-0.3,-0.5) 4(0.3,-0.5) 5(0.3,0) 6(0.3,0.5)
  silkscreen extent -0.5,-0.85 0.2,0.85, body extent -0.53,-0.75 0.53,0.75, height 0.61
DSC0010J [mm] "WSON-10"
  rrect42% 0.6x0.24 smd: 1(-1.4,1) 2(-1.4,0.5) 3(-1.4,0) 4(-1.4,-0.5) 5(-1.4,-1) 6(1.4,-1) 7(1.4,-0.5) 8(1.4,0) 9(1.4,0.5) 10(1.4,1)
  rrect12% 1.65x2.4 smd paste-1 mask-2: 11(0,0)
  Top Layer region: -0.375,-1.65 -0.375,-1.2 -0.775,-1.2 -0.794,-1.196 -0.81,-1.185 -0.821,-1.169 -0.825,-1.15 -0.825,-1.15 -0.825,1.15 -0.821,1.169 -0.81,1.185 -0.794,1.196 -0.775,1.2 -0.775,1.2 -0.375,1.2 -0.375,1.65 -0.371,1.669 -0.36,1.685 -0.344,1.696 -0.325,1.7 -0.325,1.7 -0.325,1.7 -0.175,1.7 -0.175,1.7 -0.156,1.696 -0.14,1.685 -0.129,1.669 -0.125,1.65 -0.125,1.65 -0.125,1.2 0.125,1.2 0.125,1.65 0.129,1.669 0.14,1.685 0.156,1.696 0.175,1.7 0.175,1.7 0.175,1.7 0.325,1.7 0.325,1.7 0.344,1.696 0.36,1.685 0.371,1.669 0.375,1.65 0.375,1.65 0.375,1.2 0.775,1.2 0.794,1.196 0.81,1.185 0.821,1.169 0.825,1.15 0.825,1.15 0.825,-1.15 0.821,-1.169 0.81,-1.185 0.794,-1.196 0.775,-1.2 0.775,-1.2 0.375,-1.2 0.375,-1.65 0.371,-1.669 0.36,-1.685 0.344,-1.696 0.325,-1.7 0.325,-1.7 0.175,-1.7 0.156,-1.696 0.14,-1.685 0.129,-1.669 0.125,-1.65 0.125,-1.65 0.125,-1.2 -0.125,-1.2 -0.125,-1.65 -0.129,-1.669 -0.14,-1.685 -0.156,-1.696 -0.175,-1.7 -0.175,-1.7 -0.325,-1.7 -0.344,-1.696 -0.36,-1.685 -0.371,-1.669 -0.375,-1.65
  body extent -1.5,-1.5 1.5,1.5, height 0.8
